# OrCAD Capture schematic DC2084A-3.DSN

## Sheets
1 PAGE6: size A
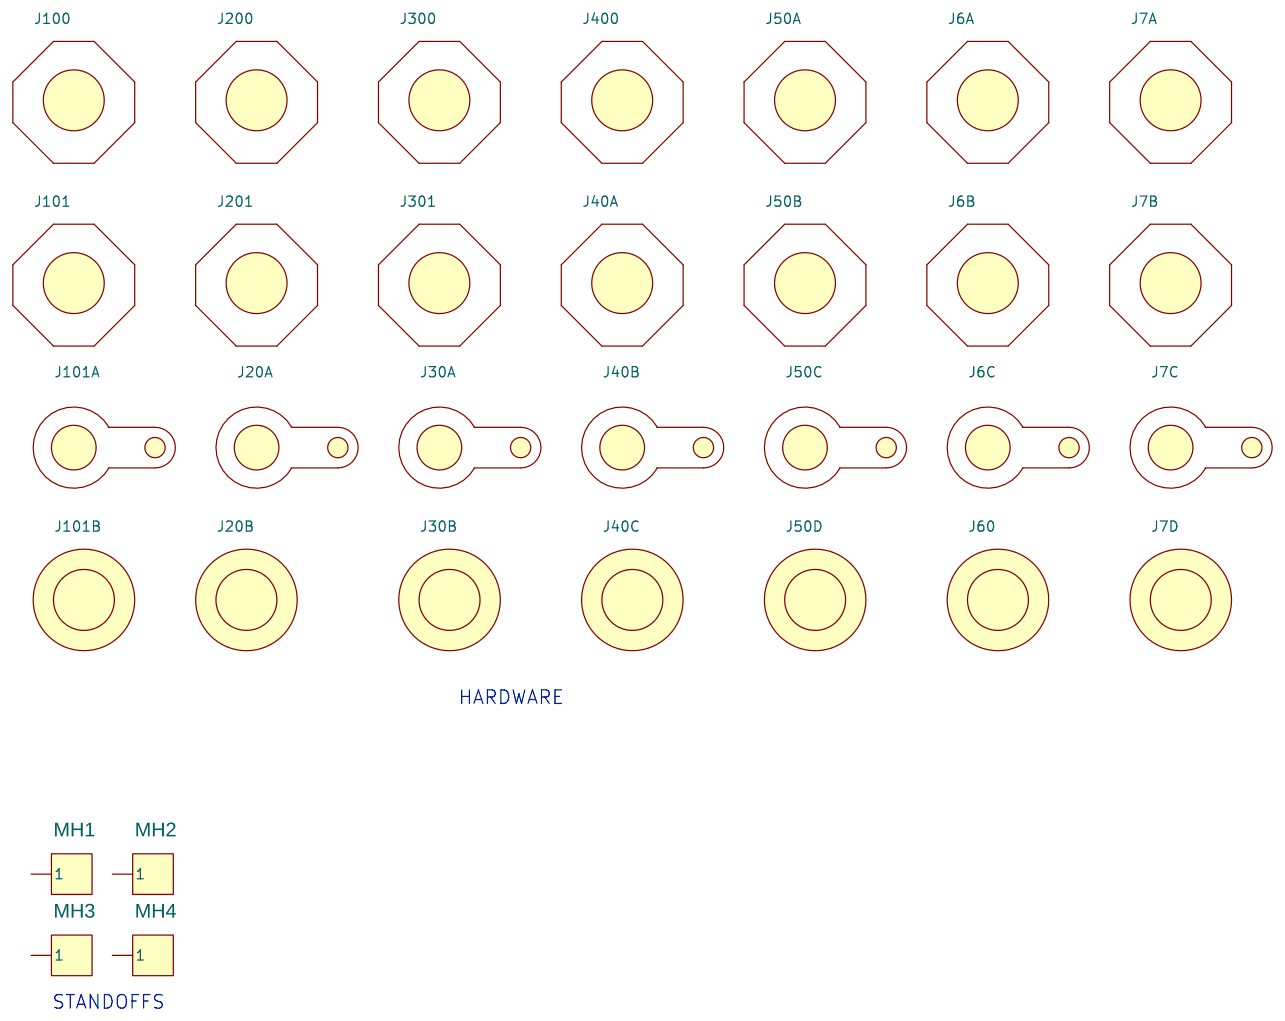
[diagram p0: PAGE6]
2 PAGE3: size Custom; title: HIGH EFFICIENCY, POLY-PHASE SYNCHRONOUS BUCK; rev: 3; company: TM; note: CONVERTER WITH POWER SYSTEM MANAGEMENT
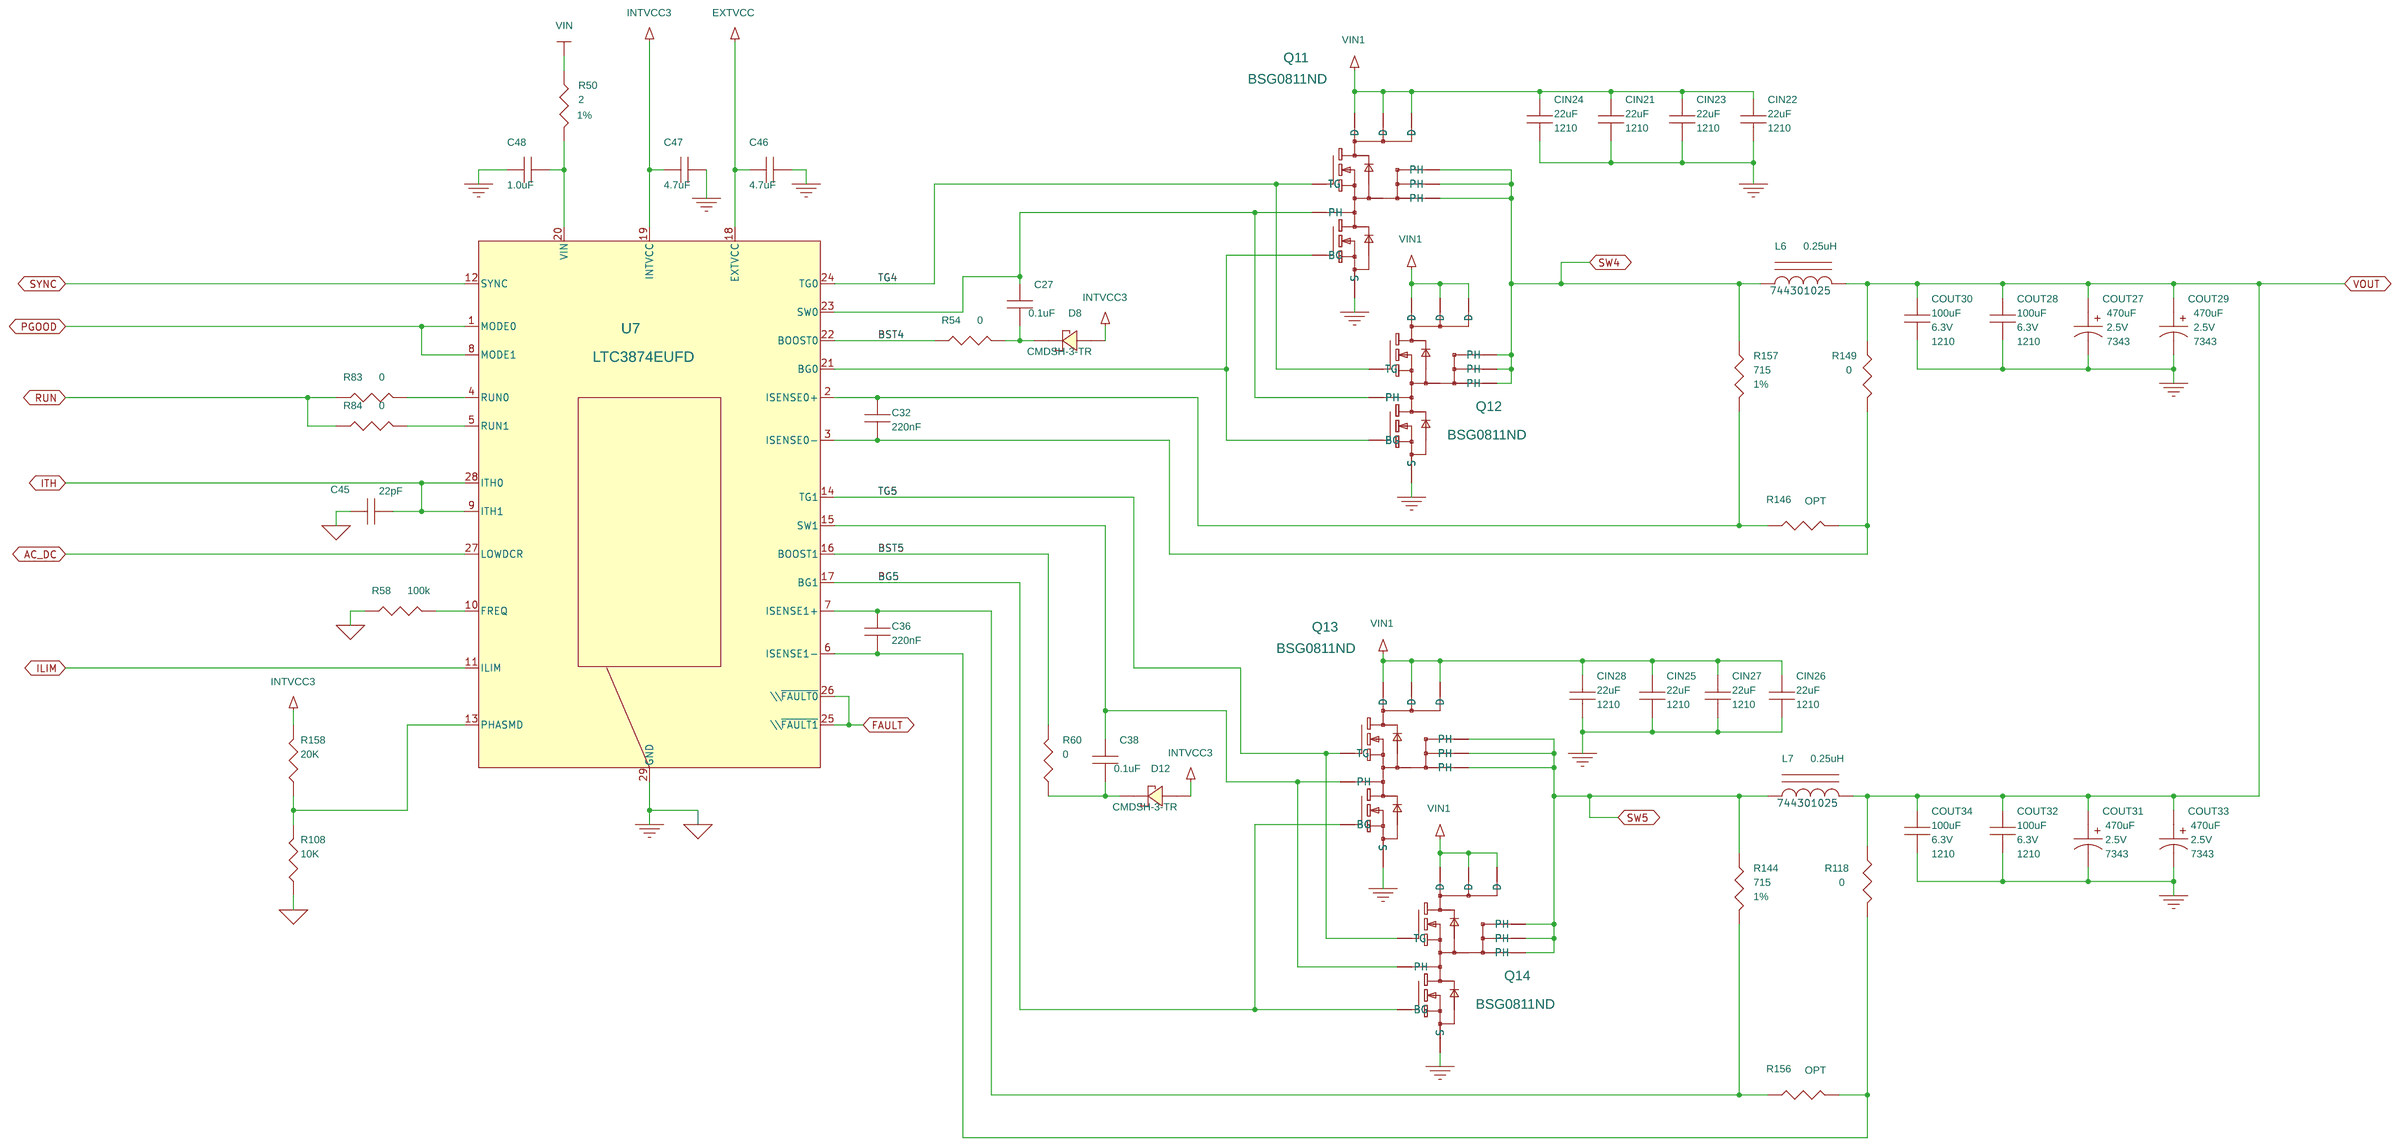
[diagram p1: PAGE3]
3 PAGE4: size B; title: HIGH EFFICIENCY, POLY-PHASE SYNCHRONOUS BUCK; rev: 3; company: TM; note: CONVERTER WITH POWER SYSTEM MANAGEMENT
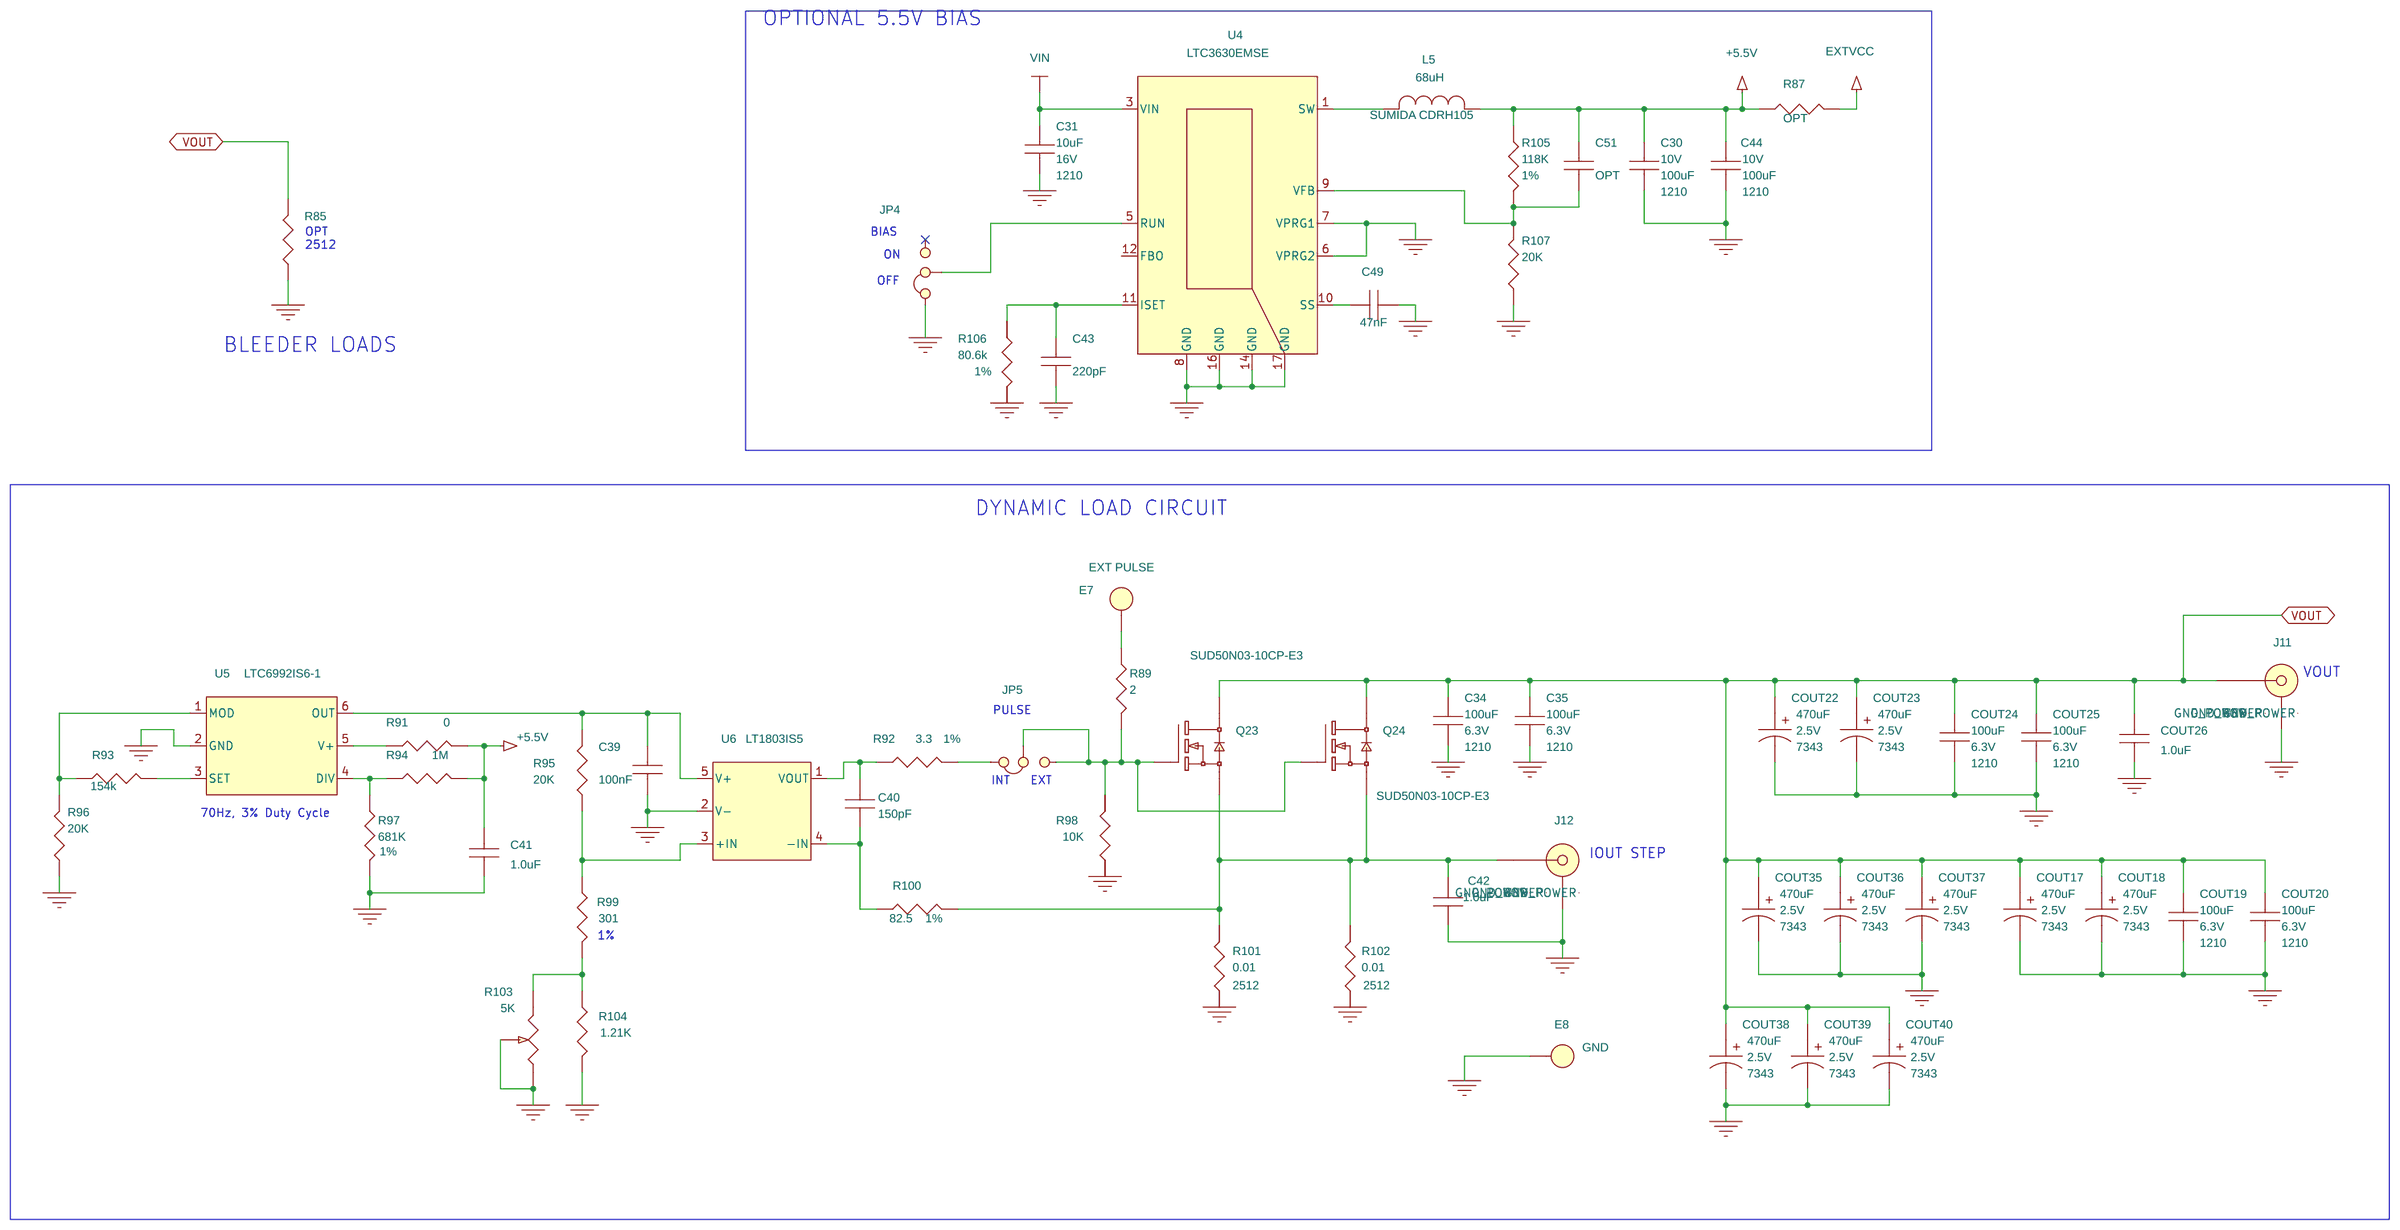
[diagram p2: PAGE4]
4 PAGE1: size Custom; title: HIGH EFFICIENCY, POLY-PHASE SYNCHRONOUS BUCK; rev: 3; company: TM; note: CONVERTER WITH POWER SYSTEM MANAGEMENT
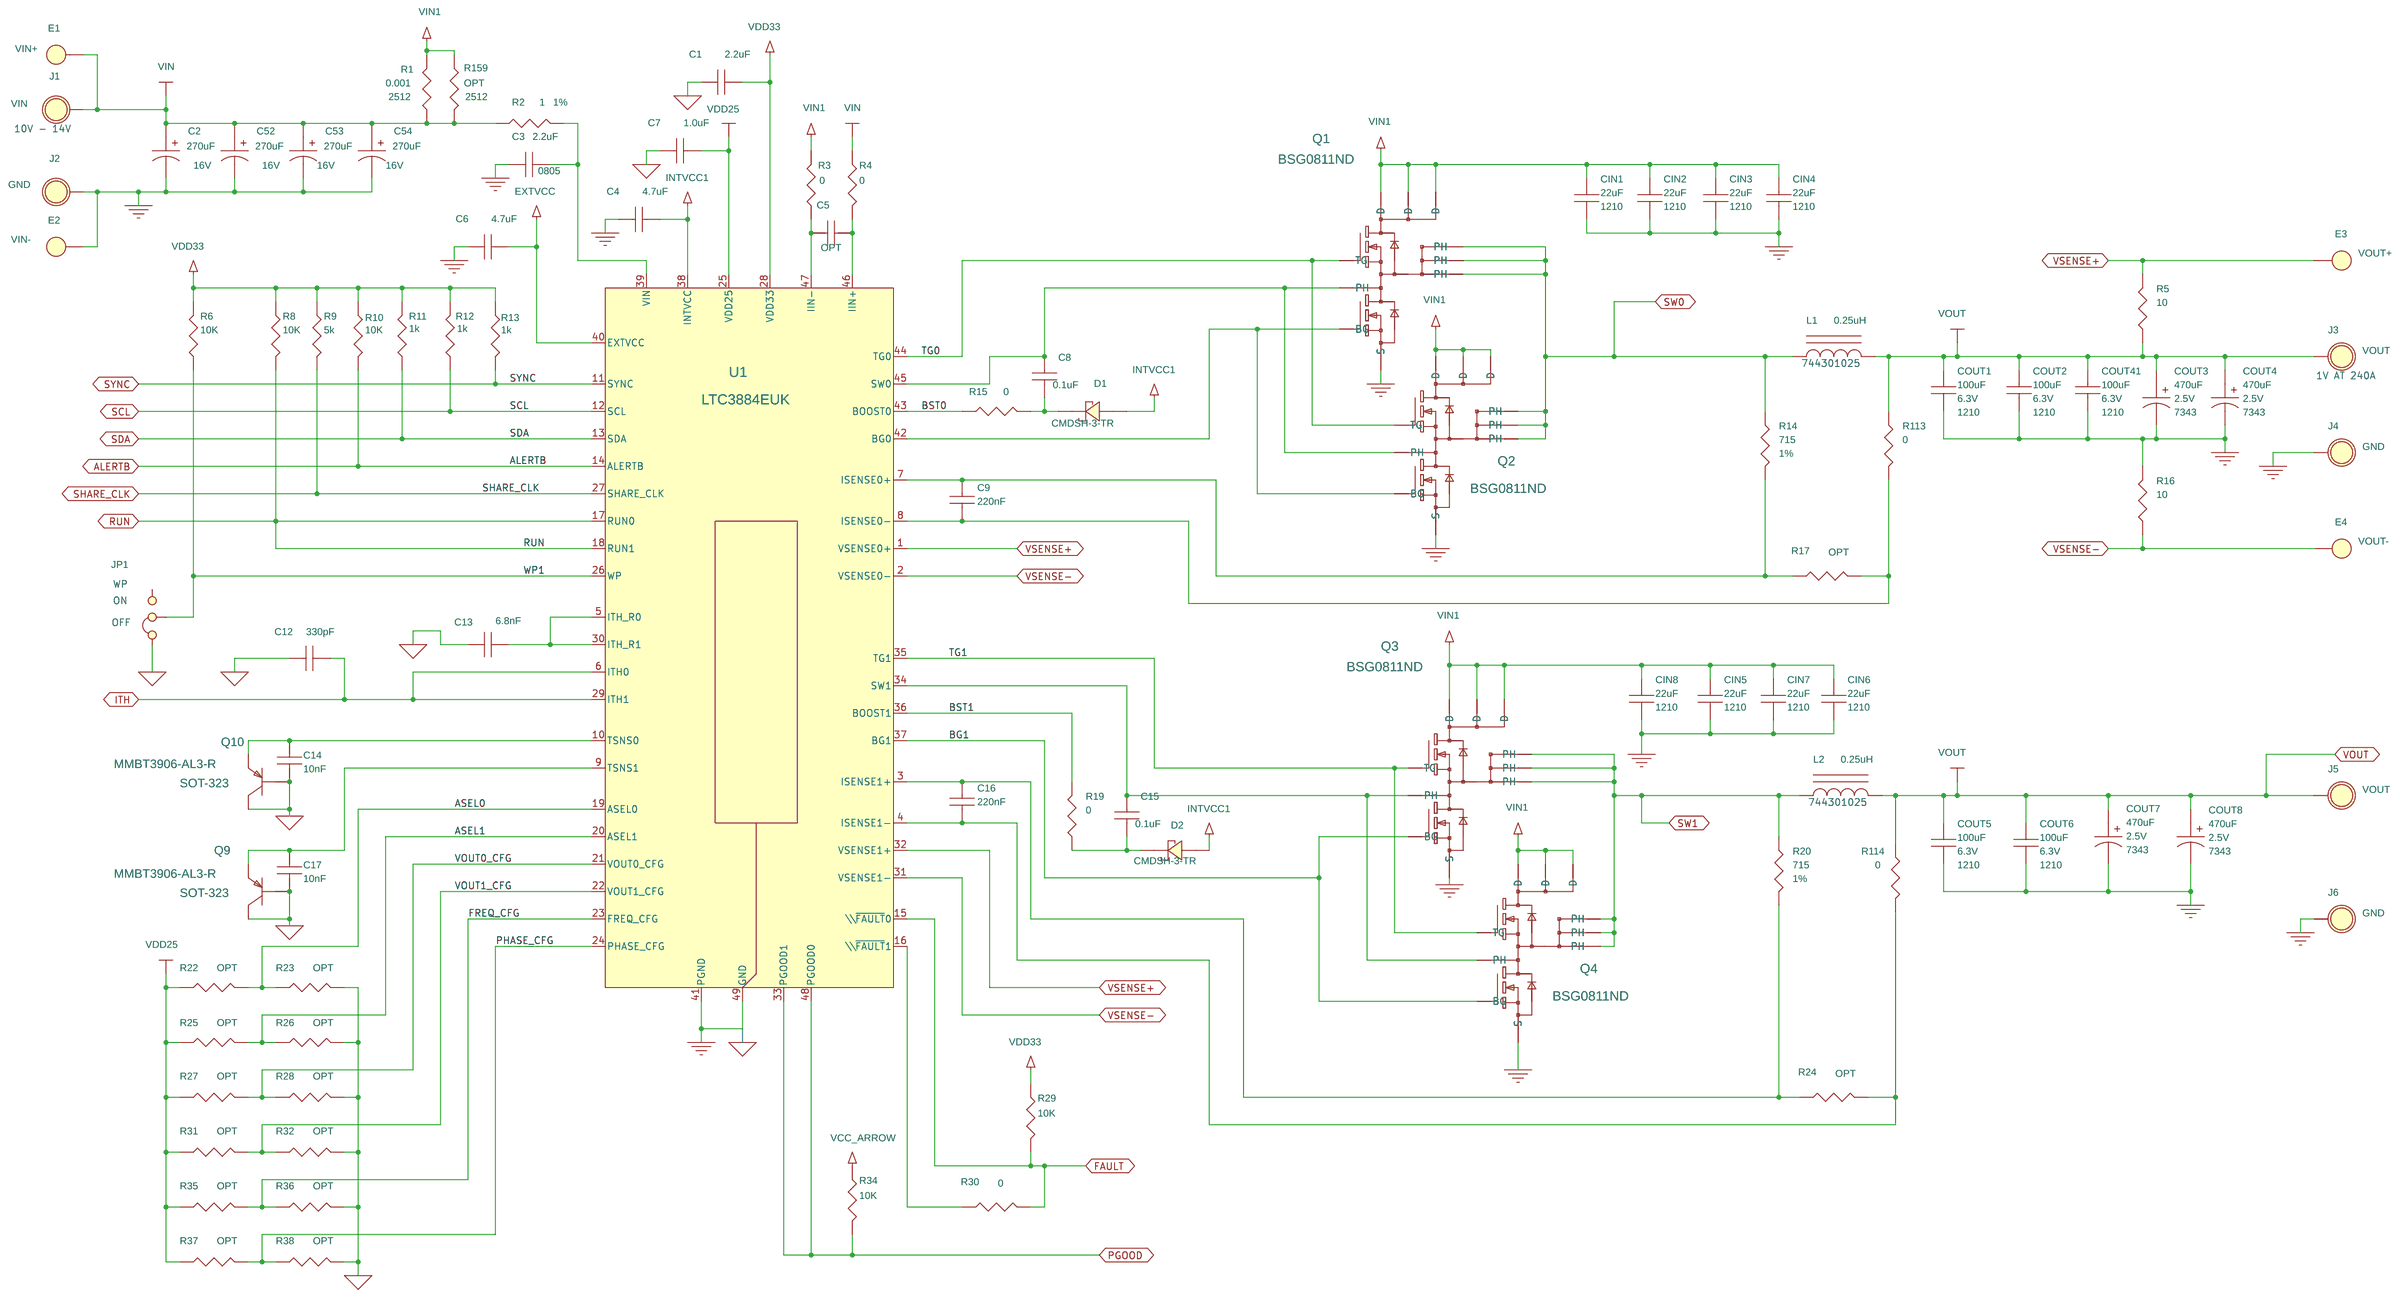
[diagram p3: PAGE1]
5 PAGE2: size Custom; title: HIGH EFFICIENCY, POLY-PHASE SYNCHRONOUS BUCK; rev: 3; company: TM; note: CONVERTER WITH POWER SYSTEM MANAGEMENT
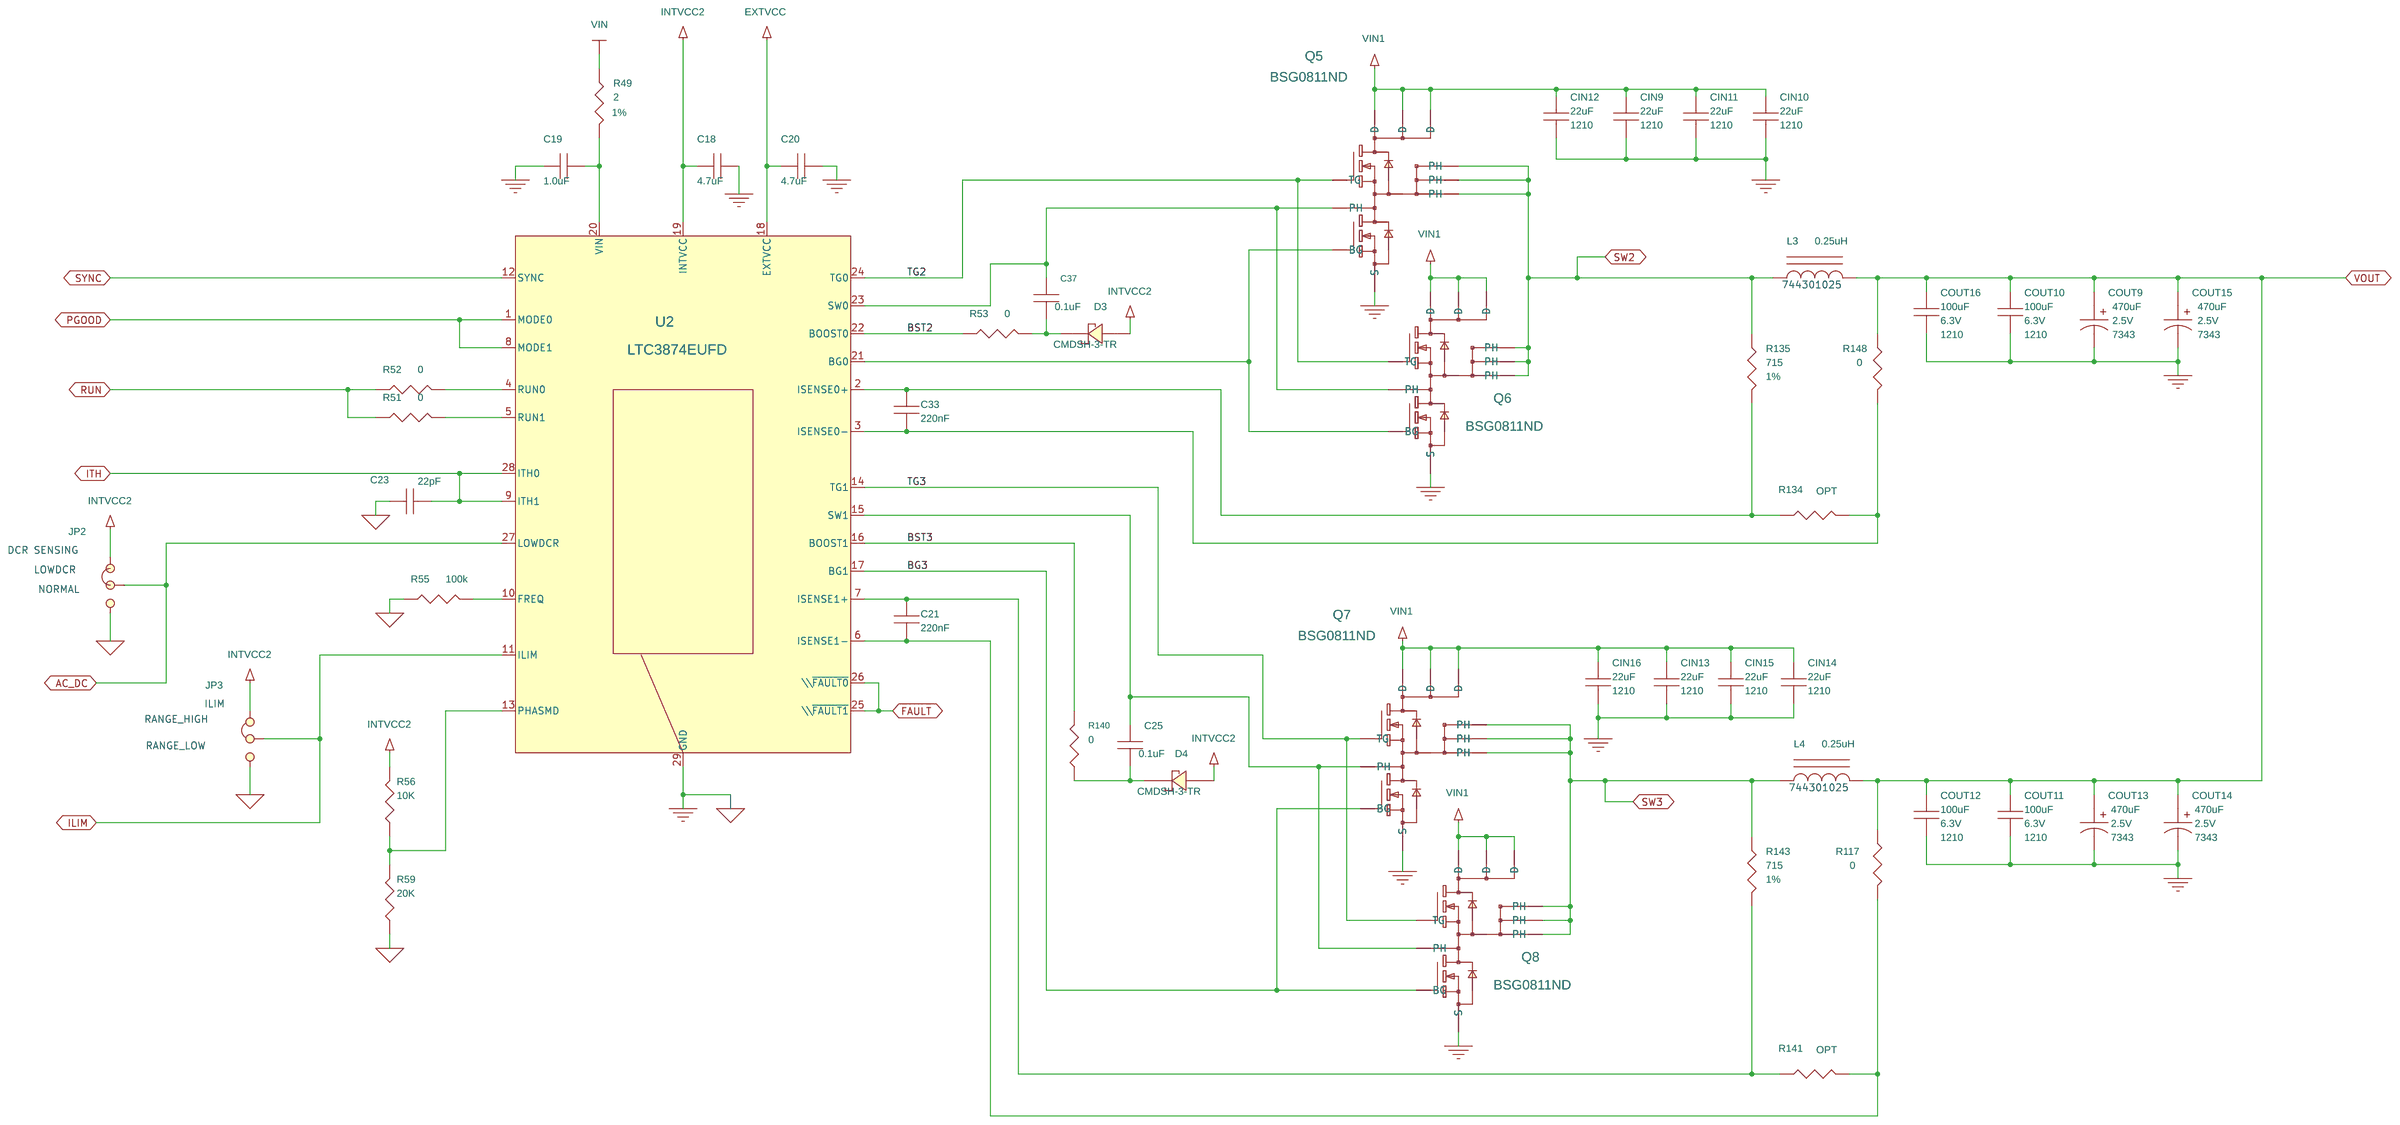
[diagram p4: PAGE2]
6 PAGE5: size B; title: HIGH EFFICIENCY, POLY-PHASE SYNCHRONOUS BUCK; rev: 3; company: TM; note: CONVERTER WITH POWER SYSTEM MANAGEMENT
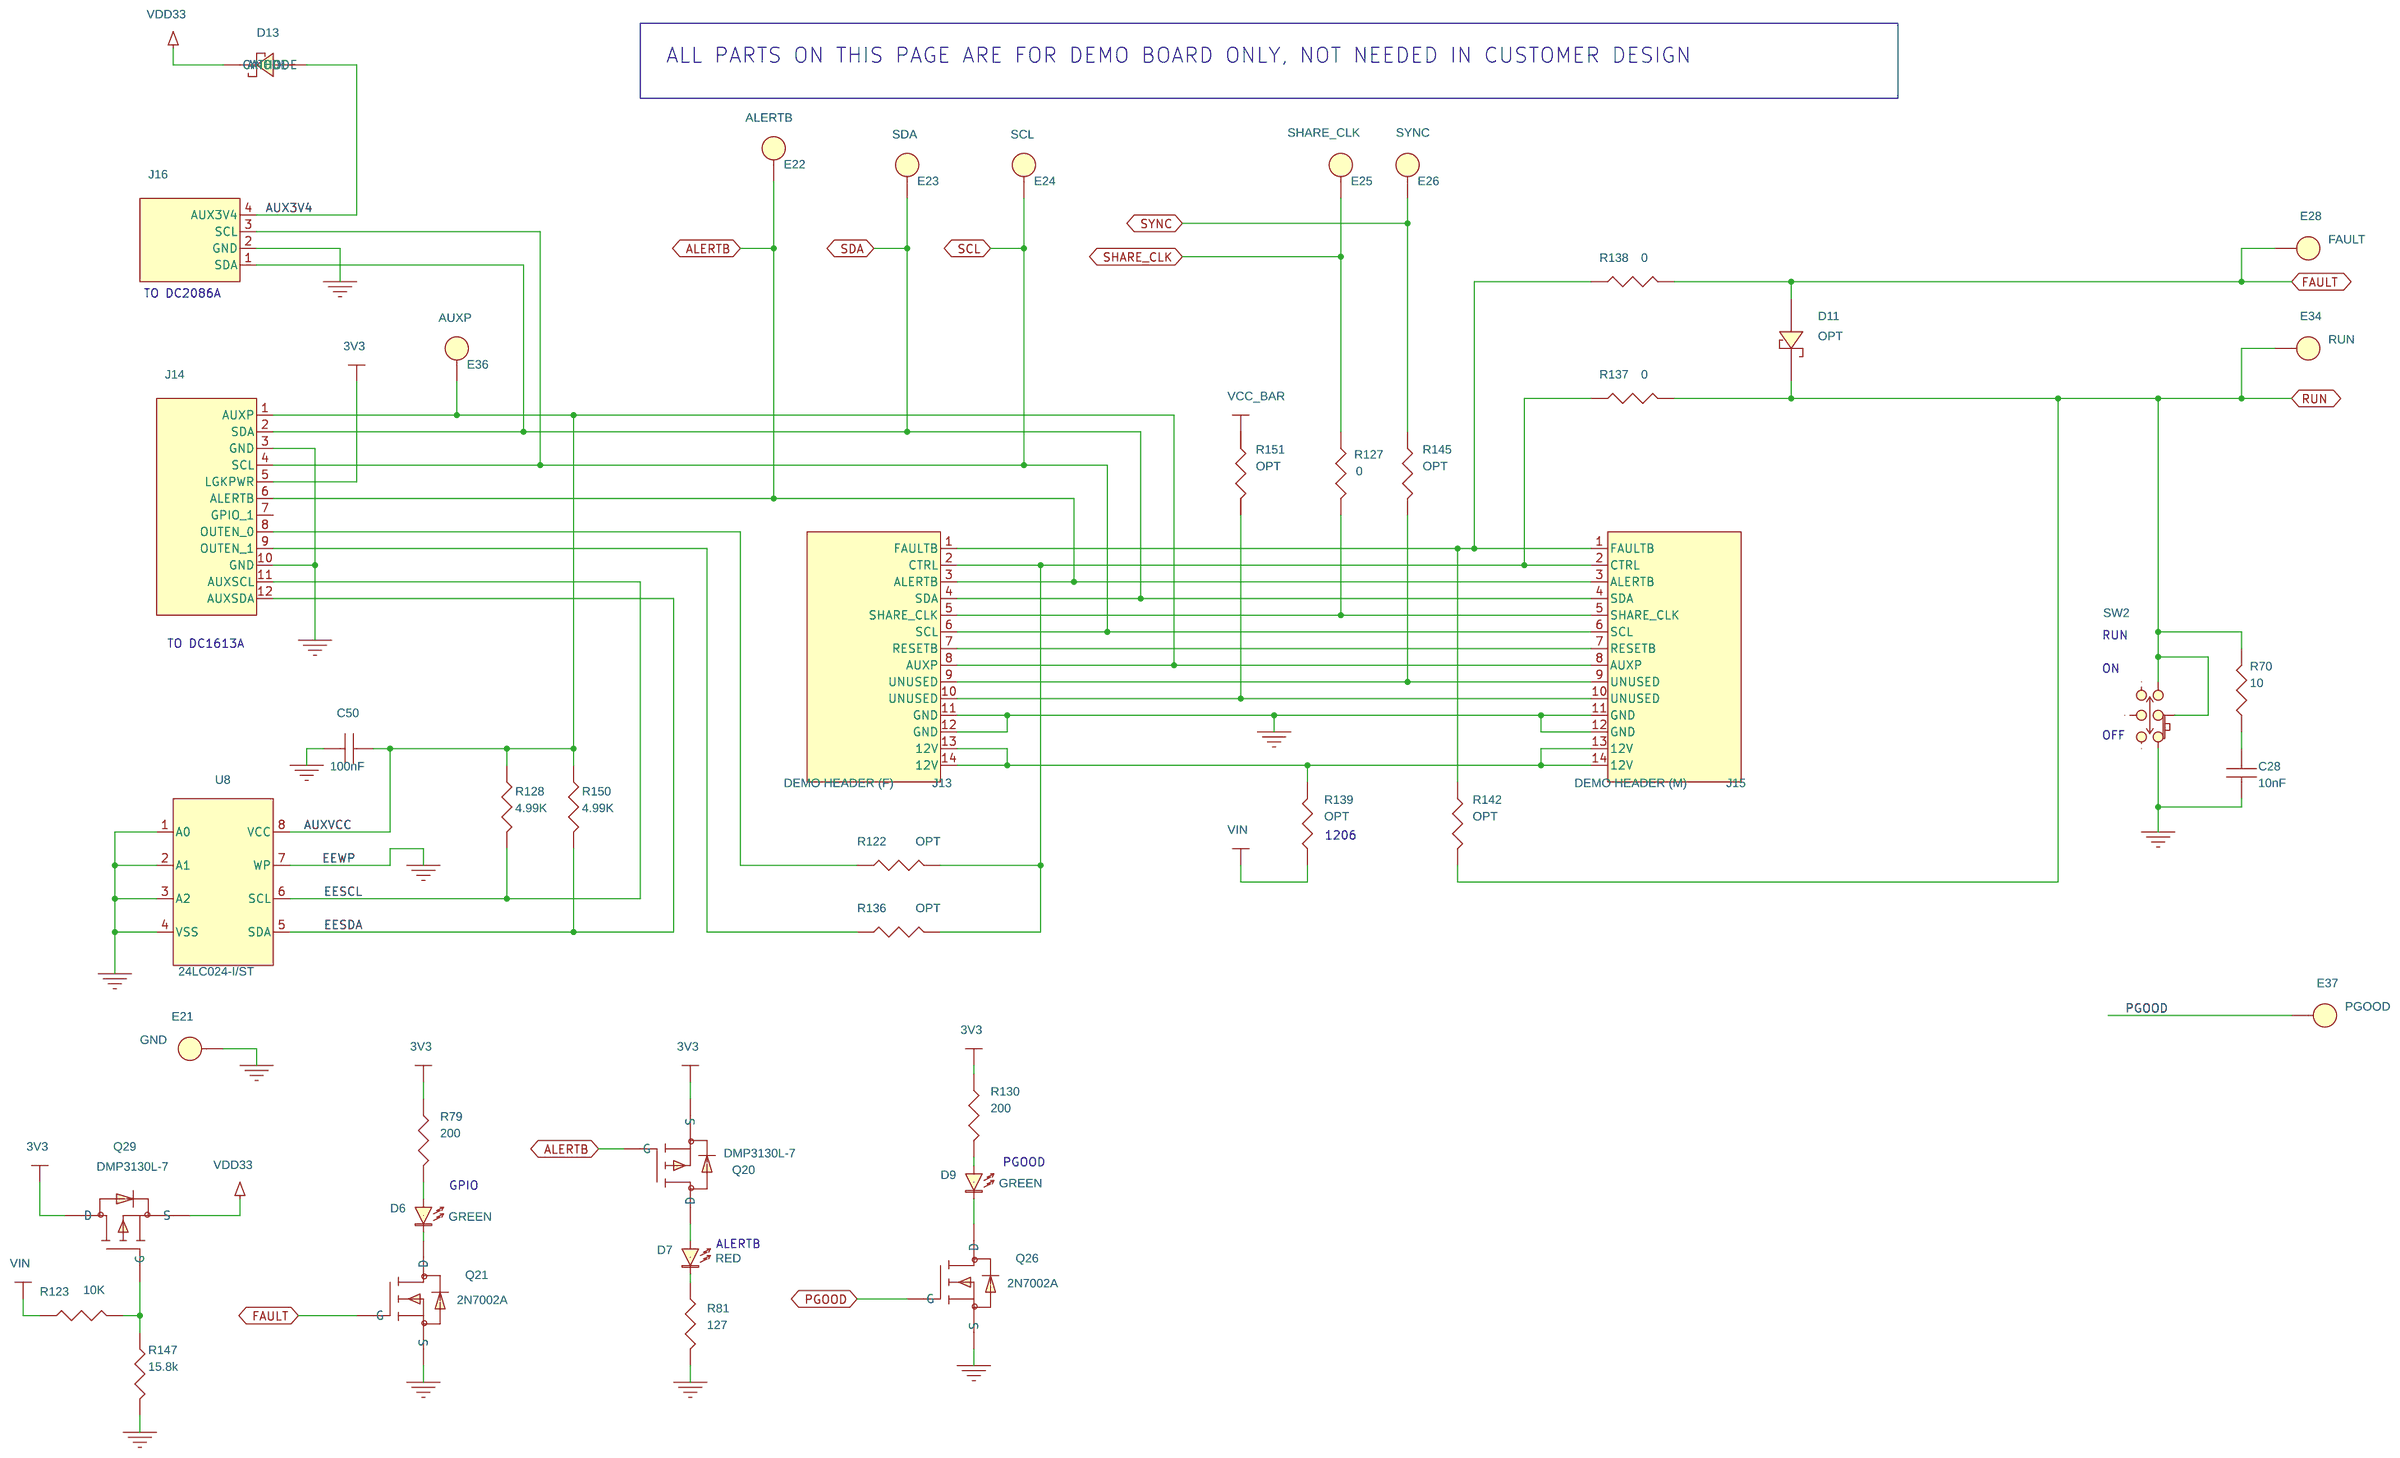
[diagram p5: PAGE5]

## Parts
sheet PAGE1
C1  2.2uF  [0603]
C2  270uF  [CAP\SAN\OSCON\SVF12]
C3  2.2uF  [0805]
C4  4.7uF  [0603]
C5  OPT  [0603]
C6  4.7uF  [0603]
C7  1.0uF  [0603]
C8  0.1uF  [0603]
C9  220nF  [0603]
C12  330pF  [0603]
C13  6.8nF  [0603]
C14  10nF  [0603]
C15  0.1uF  [0603]
C16  220nF  [0603]
C17  10nF  [0603]
C52  270uF  [CAP\SAN\OSCON\SVF12]
C53  270uF  [CAP\SAN\OSCON\SVF12]
C54  270uF  [CAP\SAN\OSCON\SVF12]
CIN1  22uF  [1210]
CIN2  22uF  [1210]
CIN3  22uF  [1210]
CIN4  22uF  [1210]
CIN5  22uF  [1210]
CIN6  22uF  [1210]
CIN7  22uF  [1210]
CIN8  22uF  [1210]
COUT1  100uF  [1210]
COUT2  100uF  [1210]
COUT3  470uF  [7343]
COUT4  470uF  [7343]
COUT5  100uF  [1210]
COUT6  100uF  [1210]
COUT7  470uF  [7343]
COUT8  470uF  [7343]
COUT41  100uF  [1210]
D1  CMDSH-3-TR  [SOD323]
D2  CMDSH-3-TR  [SOD323]
E1  VIN+  [TP\MMX\2501-2]
E2  VIN-  [TP\MMX\2501-2]
E3  VOUT+  [TP\MMX\2501-2]
E4  VOUT-  [TP\MMX\2501-2]
J1  BANANA SMALL  [CON\LUG\10]
J2  BANANA SMALL  [CON\LUG\10]
J3  BANANA SMALL  [CON\LUG\10]
J4  BANANA SMALL  [CON\LUG\10]
J5  BANANA SMALL  [CON\LUG\10]
J6  BANANA SMALL  [CON\LUG\10]
JP1  JP3X1/079\NO\12  [SIP\3P\2MM]
L1  0.25uH  [IND\WURTH\7443010XX]
L2  0.25uH  [IND\WURTH\7443010XX]
Q1  BSG0811ND  [PG-TISON8-4]
Q2  BSG0811ND  [PG-TISON8-4]
Q3  BSG0811ND  [PG-TISON8-4]
Q4  BSG0811ND  [PG-TISON8-4]
Q9  MMBT3906-AL3-R  [SOT-323]
Q10  MMBT3906-AL3-R  [SOT-323]
R1  0.001  [2512]
R2  1  [0603]
R3  0  [0603]
R4  0  [0603]
R5  10  [0603]
R6  10K  [0603]
R8  10K  [0603]
R9  5k  [0603]
R10  10K  [0603]
R11  1k  [0603]
R12  1k  [0603]
R13  1k  [0603]
R14  715  [0603]
R15  0  [0603]
R16  10  [0603]
R17  OPT  [0603]
R19  0  [0603]
R20  715  [0603]
R22  OPT  [0603]
R23  OPT  [0603]
R24  OPT  [0603]
R25  OPT  [0603]
R26  OPT  [0603]
R27  OPT  [0603]
R28  OPT  [0603]
R29  10K  [0603]
R30  0  [0603]
R31  OPT  [0603]
R32  OPT  [0603]
R34  10K  [0603]
R35  OPT  [0603]
R36  OPT  [0603]
R37  OPT  [0603]
R38  OPT  [0603]
R113  0  [0603]
R114  0  [0603]
R159  OPT  [2512]
U1  LTC3884EUK  [LT_UK48_7X7]
XJP1  SHUNT  [NONE]
sheet PAGE2
C18  4.7uF  [0603]
C19  1.0uF  [0603]
C20  4.7uF  [0603]
C21  220nF  [0603]
C23  22pF  [0603]
C25  0.1uF  [0603]
C33  220nF  [0603]
C37  0.1uF  [0603]
CIN9  22uF  [1210]
CIN10  22uF  [1210]
CIN11  22uF  [1210]
CIN12  22uF  [1210]
CIN13  22uF  [1210]
CIN14  22uF  [1210]
CIN15  22uF  [1210]
CIN16  22uF  [1210]
COUT9  470uF  [7343]
COUT10  100uF  [1210]
COUT11  100uF  [1210]
COUT12  100uF  [1210]
COUT13  470uF  [7343]
COUT14  470uF  [7343]
COUT15  470uF  [7343]
COUT16  100uF  [1210]
D3  CMDSH-3-TR  [SOD323]
D4  CMDSH-3-TR  [SOD323]
JP2  JP3X1/079\NO\12  [SIP\3P\2MM]
JP3  JP3X1/079\NO\12  [SIP\3P\2MM]
L3  0.25uH  [IND\WURTH\7443010XX]
L4  0.25uH  [IND\WURTH\7443010XX]
Q5  BSG0811ND  [PG-TISON8-4]
Q6  BSG0811ND  [PG-TISON8-4]
Q7  BSG0811ND  [PG-TISON8-4]
Q8  BSG0811ND  [PG-TISON8-4]
R49  2  [0603]
R51  0  [0603]
R52  0  [0603]
R53  0  [0603]
R55  100k  [0603]
R56  10K  [0603]
R59  20K  [0603]
R117  0  [0603]
R134  OPT  [0603]
R135  715  [0603]
R140  0  [0603]
R141  OPT  [0603]
R143  715  [0603]
R148  0  [0603]
U2  LTC3874EUFD  [LT_UFD28_4X5]
XJP2  SHUNT  [NONE]
XJP3  SHUNT  [NONE]
sheet PAGE3
C27  0.1uF  [0603]
C32  220nF  [0603]
C36  220nF  [0603]
C38  0.1uF  [0603]
C45  22pF  [0603]
C46  4.7uF  [0603]
C47  4.7uF  [0603]
C48  1.0uF  [0603]
CIN21  22uF  [1210]
CIN22  22uF  [1210]
CIN23  22uF  [1210]
CIN24  22uF  [1210]
CIN25  22uF  [1210]
CIN26  22uF  [1210]
CIN27  22uF  [1210]
CIN28  22uF  [1210]
COUT27  470uF  [7343]
COUT28  100uF  [1210]
COUT29  470uF  [7343]
COUT30  100uF  [1210]
COUT31  470uF  [7343]
COUT32  100uF  [1210]
COUT33  470uF  [7343]
COUT34  100uF  [1210]
D8  CMDSH-3-TR  [SOD323]
D12  CMDSH-3-TR  [SOD323]
L6  0.25uH  [IND\WURTH\7443010XX]
L7  0.25uH  [IND\WURTH\7443010XX]
Q11  BSG0811ND  [PG-TISON8-4]
Q12  BSG0811ND  [PG-TISON8-4]
Q13  BSG0811ND  [PG-TISON8-4]
Q14  BSG0811ND  [PG-TISON8-4]
R50  2  [0603]
R54  0  [0603]
R58  100k  [0603]
R60  0  [0603]
R83  0  [0603]
R84  0  [0603]
R108  10K  [0603]
R118  0  [0603]
R144  715  [0603]
R146  OPT  [0603]
R149  0  [0603]
R156  OPT  [0603]
R157  715  [0603]
R158  20K  [0603]
U7  LTC3874EUFD  [LT_UFD28_4X5]
sheet PAGE4
C30  100uF  [1210]
C31  10uF  [1210]
C34  100uF  [1210]
C35  100uF  [1210]
C39  100nF  [0603]
C40  150pF  [0603]
C41  1.0uF  [0603]
C42  1.0uF  [0603]
C43  220pF  [0603]
C44  100uF  [1210]
C49  47nF  [0603]
C51  OPT  [0603]
COUT17  470uF  [7343]
COUT18  470uF  [7343]
COUT19  100uF  [1210]
COUT20  100uF  [1210]
COUT22  470uF  [7343]
COUT23  470uF  [7343]
COUT24  100uF  [1210]
COUT25  100uF  [1210]
COUT26  1.0uF  [0603]
COUT35  470uF  [7343]
COUT36  470uF  [7343]
COUT37  470uF  [7343]
COUT38  470uF  [7343]
COUT39  470uF  [7343]
COUT40  470uF  [7343]
E7  EXT PULSE  [TP\MMX\2501-2]
E8  GND  [TP\MMX\2501-2]
J11  XXX  [BNC5]
J12  XXX  [BNC5]
JP4  JP3X1/079\NO\12  [SIP\3P\2MM]
JP5  JP3X1/079\NO\12  [SIP\3P\2MM]
L5  68uH  [IND\SUMIDA\CDRH105R\12X12]
Q23  SUD50N03-10CP-E3  [TO-252]
Q24  SUD50N03-10CP-E3  [TO-252]
R85  OPT  [2512]
R87  OPT  [0603]
R89  2  [0603]
R91  0  [0603]
R92  3.3  [0603]
R93  154k  [0603]
R94  1M  [0603]
R95  20K  [0603]
R96  20K  [0603]
R97  681K  [0603]
R98  10K  [0603]
R99  301  [0603]
R100  82.5  [0603]
R101  0.01  [2512]
R102  0.01  [2512]
R103  5K  [BOURNS_3386P]
R104  1.21K  [0603]
R105  118K  [0603]
R106  80.6k  [0603]
R107  20K  [0603]
U4  LTC3630EMSE  [MSE-16L(12)]
U5  LTC6992IS6-1  [LT_S6]
U6  LT1803IS5  [LT_S5]
XJP4  SHUNT  [NONE]
XJP5  SHUNT  [NONE]
sheet PAGE5
C28  10nF  [0603]
C50  100nF  [0603]
D6  GREEN  [LED_0603]
D7  RED  [LED_0603]
D9  GREEN  [LED_0603]
D11  OPT  [SOD323]
D13  DIODE SCHOTTKY  [SOD882]
E21  GND  [TP\MMX\2501-2]
E22  ALERTB  [TP\MMX\2501-2]
E23  SDA  [TP\MMX\2501-2]
E24  SCL  [TP\MMX\2501-2]
E25  SHARE_CLK  [TP\MMX\2501-2]
E26  SYNC  [TP\MMX\2501-2]
E28  FAULT  [TP\MMX\2501-2]
E34  RUN  [TP\MMX\2501-2]
E36  AUXP  [TP\MMX\2501-2]
E37  PGOOD  [TP\MMX\2501-2]
J13  DEMO HEADER (F)  [NPPN072FJFN-RC]
J14  HD2X6-079  [HD2X6-079-MOLEX]
J15  DEMO HEADER (M)  [NPPN072FJFN]
J16  HD2X6-079-PMBUS_0  [CON\HRS\DF3A-4P-2DSA]
Q20  DMP3130L-7  [SOT23]
Q21  2N7002A  [SOT23]
Q26  2N7002A  [SOT23]
Q29  DMP3130L-7  [SOT23]
R70  10  [0603]
R79  200  [0603]
R81  127  [0603]
R122  OPT  [0603]
R123  10K  [0603]
R127  0  [0603]
R128  4.99K  [0603]
R130  200  [0603]
R136  OPT  [0603]
R137  0  [0603]
R138  0  [0603]
R139  OPT  [1206]
R142  OPT  [0603]
R145  OPT  [0603]
R147  15.8k  [0603]
R150  4.99K  [0603]
R151  OPT  [0603]
SW2  JP3X1/079\NO\12  [JS202011]
U8  24LC024-I/ST  [TSSOP-8_4.4MM]
sheet PAGE6
J6A  NUT
J6B  NUT
J6C  Lug_Ring
J7A  NUT
J7B  NUT
J7C  Lug_Ring
J7D  Washer
J20A  Lug_Ring
J20B  Washer
J30A  Lug_Ring
J30B  Washer
J40A  NUT
J40B  Lug_Ring
J40C  Washer
J50A  NUT
J50B  NUT
J50C  Lug_Ring
J50D  Washer
J60  Washer
J100  NUT
J101  NUT
J101A  Lug_Ring
J101B  Washer
J200  NUT
J201  NUT
J300  NUT
J301  NUT
J400  NUT
MH1  CON1  [KEYSTONE_8831]
MH2  CON1  [KEYSTONE_8831]
MH3  CON1  [KEYSTONE_8831]
MH4  CON1  [KEYSTONE_8831]

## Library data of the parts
C1 = CAP_NP: CAP, 0603 2.2uF 20% 6.3V X5R; Part Number: TAIYO YUDEN JMK105BJ225MV-T; Volts/Amps/Watts: 50V
C2 C52-C54 = CAPR12X5_0: CAP, 270uF 20% 16V OSCON; Component: cap; Manufacturer: SANYO; Part Number: PANASONIC 16SVPC270M; Tolerance: 20%; Type: OS-CON; Volts/Amps/Watts: 16V
C3 = CAP_NP_0: CAP, 0805 2.2uF 10% 16V X7R; Part Number: MURATA GRM21BR71C225KA12L; VOLTAGE: 16V
C4 C6 C18 C20 C46 C47 = CAP_NP: CAP, 0603 4.7uF 10% 10V X5R; Part Number: AVX 0603ZD475KAT2A
C5 C51 = CAP_NP: CAP, 0603 OPTION; Part Number: OPTION
C7 C19 C41 C48 COUT26 = CAP_NP: CAP, 0603 1uF 20% 25V X5R; Part Number: AVX 06033D105MAT2A
C8 C15 C25 C27 C37 C38 = CAP_NP_0: CAP, 0603 0.1uF 10% 25V X5R; Part Number: AVX 06033C104KAT2A; VOLTAGE: 50V
C9 C16 C21 C32 C33 C36 = CAP_NP: CAP, 0603 220nF 10% 25V X7R; Part Number: TDK C1608X7R1E224K
C12 = CAP_NP: CAP, 0603 330pF 5% 50V C0G; Part Number: MURATA GRM1885C1H331JD01D
C13 = CAP_NP: CAP, 0603 6.8nF 10% 50V X7R; Part Number: MURATA GRM188R71H682KA01B
C14 C17 C28 = CAP_NP: CAP, 0603 10nF 10% 25V X7R; Part Number: AVX 06033C103KAT2A
CIN1-CIN16 CIN21-CIN28 = CAP_NP_0: CAP, 1210 22uF 10% 25V X7R; Part Number: MURATA GRM32ER71E226KE15L; VOLTAGE: 50V; Volts/Amps/Watts: 6.3V
C34 C35 COUT1 COUT2 COUT5 COUT6 COUT10-COUT12 COUT16 COUT19 COUT20 COUT24 COUT25 COUT28 COUT30 COUT32 COUT34 COUT41 = CAP_NP_0: CAP, 1210 100uF 20% 6.3V X5R; Part Number: TDK C3225X5R0J107M; VOLTAGE: 50V; Volts/Amps/Watts: 6.3V
COUT3 COUT4 COUT7-COUT9 COUT13-COUT15 COUT17 COUT18 COUT22 COUT23 COUT27 COUT29 COUT31 COUT33 COUT35-COUT40 = t510x337k010as: CAP, 7343 470uF 20% 2.5V TANT. POLYMER; 1st Part Field: 2.5V; 3rd Part Field: POSCAP; Part Number: PANASONIC ETPF470M5H
D1-D4 D8 D12 = DIODE_SCHOTTKY_9: DIODE, SCHOTTKY 30V, 100mA; Part Number: CENTRAL SEMI CMDSH-3-TR
E1-E4 E7 E8 E21-E26 E28 E34 E36 E37 = E_0: TURRET; Part Number: MILL MAX 2501-2-00-80-00-00-07-0
J1 = BANANA_SMALL_0: STUD, TEST PIN; Component: conn; Label: VIN; Part Number: PEM KFH-032-10
J2 J4 J6 = BANANA_SMALL_0: STUD, TEST PIN; Component: conn; Label: GND; Part Number: PEM KFH-032-10
J3 J5 = BANANA_SMALL_0: STUD, TEST PIN; Component: conn; Label: VOUT; Part Number: PEM KFH-032-10
JP1-JP5 = JP3X1_079_NO_12_1: HEADER, SINGLE ROW 3PIN; Part Number: WURTH ELEKTRONIK 60800213421
L1-L4 L6 L7 = INDUCTOR_IRON: IND, 0.25uH; Part Number: WURTH ELEKTRONIK 744301025
Q1-Q8 Q11-Q14 = FDMS3610S_3: XSTR, DUAL CHANNEL OptiMOS MOSFET; Part Number: INFINEON BSG0811ND
Q9 Q10 = MMBT3906_SOT_0: XSTR, PNP GENERAL PURPOSE; Part Number: DIODES INC. MMST3906-7-F
R1 = RES0603_0: RES, 2512 0.001 OHMS 1% 1W; Label: 2; Manufacturer: Rohm; Manufacturer P/N: RHM0.0GCT-ND; Part Number: VISHAY WSL25121L000FEA; Vendor: Digikey; Vendor P/N: RHM0.0GCT-ND; Volts/Amps/Watts: 0.1W
R2 = RES0603_0: RES, 0603 1 OHMS 1% 1/10W; Component: res; Label: <label>; Manufacturer: Panasonic; Manufacturer P/N: ERJ-3EKF5901V; Part Number: VISHAY CRCW06031R00FNEA; Tolerance: 1%; Vendor: Digikey; Vendor P/N: P5.90KHCT-ND; Volts/Amps/Watts: 0.1W
R3 R127 = RES0603_0: RES, 0603 0 OHMS JUMPER; Manufacturer: Rohm; Manufacturer P/N: RHM0.0GCT-ND; Part Number: VISHAY CRCW06030000Z0EA; Tolerance: 5%; Vendor: Digikey; Vendor P/N: RHM0.0GCT-ND; Volts/Amps/Watts: 0.1W
R4 = RES0603_0: RES, 0603 0 OHMS JUMPER; Manufacturer: ROHM; Manufacturer P/N: MCR03EZPFX1002; Part Number: VISHAY CRCW06030000Z0EA; Vendor: Digikey; Vendor P/N: RHM10.0KHCT-ND; Volts/Amps/Watts: 0.1W
R5 = RES0603_0: RES, 0603 10 OHMS 1% 0.1W; Manufacturer: Yageo; Manufacturer P/N: RC0603JR-070RL; Part Number: VISHAY CRCW060310R0FKEA; Tolerance: 1%; Vendor: Digikey; Vendor P/N: 311-0.0GRCT-ND; Volts/Amps/Watts: 0.1W
R6 R56 R108 = RES0603_0: RES, 0603 10K OHMS 5% 0.1W; Manufacturer: Panasonic; Manufacturer P/N: ERJ-3EKF2002V; Part Number: VISHAY CRCW060310K0JNEA; Vendor: Digikey; Vendor P/N: P20.0KHCT-ND; Volts/Amps/Watts: 0.1W
R8 R10 = RES0603_0: RES, 0603 10K OHMS 5% 0.1W; Manufacturer: ROHM; Manufacturer P/N: MCR03EZPFX1002; Part Number: VISHAY CRCW060310K0JNEA; Vendor: Digikey; Vendor P/N: RHM10.0KHCT-ND; Volts/Amps/Watts: 0.1W
R9 = RES0603_0: RES, 0603 5k OHMS 5% 0.1W; Manufacturer: ROHM; Manufacturer P/N: MCR03EZPFX1002; Part Number: VISHAY CRCW06035K00JNED; Vendor: Digikey; Vendor P/N: RHM10.0KHCT-ND; Volts/Amps/Watts: 0.1W
R11-R13 = RES0603_0: RES, 0603 1K OHMS 5% 0.1W; Manufacturer: ROHM; Manufacturer P/N: MCR03EZPFX1002; Part Number: VISHAY CRCW06031K00JNEA; Vendor: Digikey; Vendor P/N: RHM10.0KHCT-ND; Volts/Amps/Watts: 0.1W
R14 R135 R157 = R_1: RES, 0603 715 OHMS 1% 0.1W; %: 0.1%; Part Number: VISHAY CRCW0603715RFKEA; Tol: 1%
R15 R19 R51-R54 R60 R83 R84 R91 R140 = RES0603_0: RES, 0603 0 OHMS JUMPER; Component: res; Label: <label>; Manufacturer: Panasonic; Manufacturer P/N: ERJ-3EKF5901V; Part Number: VISHAY CRCW06030000Z0EA; Tolerance: 1%; Vendor: Digikey; Vendor P/N: P5.90KHCT-ND; Volts/Amps/Watts: 0.1W
R16 = RES0603_0: RES, 0603 10 OHMS 1% 1/10W; Manufacturer: Yageo; Manufacturer P/N: RC0603JR-070RL; Part Number: VISHAY CRCW060310R0FKEA; Tolerance: 1%; Vendor: Digikey; Vendor P/N: 311-0.0GRCT-ND; Volts/Amps/Watts: 0.1W
R17 R24 R134 R141 R146 R156 = R_1: RES, 0603 OPTION; %: 0.1%; Part Number: OPTION
R20 = R_1: RES, 0603 715 OHMS 1% 0.1W; %: 1%; Part Number: VISHAY CRCW0603715RFKEA
R22 R28 R32 R36 R38 = RES0603_0: RES, 0603 OPTION; Manufacturer: Panasonic; Manufacturer P/N: ERJ-3EKF2002V; Part Number: OPTION; Vendor: Digikey; Vendor P/N: P20.0KHCT-ND; Volts/Amps/Watts: 0.1W
R23 = RES0603_0: RES, 0603 OPTION; Manufacturer: Rohm; Manufacturer P/N: RHM0.0GCT-ND; Part Number: OPTION; Tolerance: 5%; Vendor: Digikey; Vendor P/N: RHM0.0GCT-ND; Volts/Amps/Watts: 0.1W
R25 = RES0603_0: RES, 0603 OPTION; Manufacturer: Panasonic; Manufacturer P/N: ERJ-3EKF5901V; Part Number: OPTION; Vendor: Digikey; Vendor P/N: P5.90KHCT-ND; Volts/Amps/Watts: 0.1W
R26 = RES0603_0: RES, 0603 OPTION; Manufacturer: Panasonic; Manufacturer P/N: ERJ-3EKF2002V; Part Number: OPTION; Tolerance: 5%; Vendor: Digikey; Vendor P/N: P20.0KHCT-ND; Volts/Amps/Watts: 0.1W
R27 = RES0603_0: RES, 0603 OPTION; Manufacturer: Panasonic; Manufacturer P/N: ERJ-3EKF1000V; Part Number: OPTION; Vendor: Digikey; Vendor P/N: P100HCT-ND; Volts/Amps/Watts: 0.1W
R29 R34 = RES0603_0: RES, 0603 10K OHMS 5% .01W; Manufacturer: Panasonic; Manufacturer P/N: ERJ-3EKF2002V; Part Number: VISHAY CRCW060310K0JNEA; Vendor: Digikey; Vendor P/N: P20.0KHCT-ND; Volts/Amps/Watts: 0.1W
R30 = R_1: RES, 0603 0 OHMS JUMPER; %: 0.1%; Part Number: VISHAY CRCW06030000Z0EA
R31 = RES0603_0: RES, 0603 OPTION; Manufacturer: Panasonic; Manufacturer P/N: ERJ-3EKF1021V; Part Number: OPTION; Vendor: Digikey; Vendor P/N: P1.02KHCT-ND; Volts/Amps/Watts: 0.1W
R35 R37 = RES0603_0: RES, 0603 OPTION; Manufacturer: ROHM; Manufacturer P/N: MCR03EZPFX1002; Part Number: OPTION; Vendor: Digikey; Vendor P/N: RHM10.0KHCT-ND; Volts/Amps/Watts: 0.1W
R113 R114 R117 R118 R148 R149 = R_1: RES, 0603 0 OHMS JUMPER; %: 0.1%; Part Number: VISHAY CRCW06030000Z0EA; Tol: 1%
R159 = RES0603_0: RES, 2512 OPTION; Label: 2; Manufacturer: Rohm; Manufacturer P/N: RHM0.0GCT-ND; Part Number: OPTION; Vendor: Digikey; Vendor P/N: RHM0.0GCT-ND; Volts/Amps/Watts: 0.1W
U1 = LTC3880-M0001_9: IC, DUAL OUTPUT STEP-DOWN CONTROLLER; Component: IC; Manufacturer: LTC; Manufacturer P/N: LTC3880_M0001; Part Number: LINEAR TECH. LTC3884EUK
XJP1-XJP5 = SHUNT: Part Number: WURTH ELEKTRONIK 60800213421
C23 C45 = CAP_NP: CAP, 0603 22pF 5% 50V C0G; Part Number: MURATA GRM1885C1H220JA01B
R49 R50 = RES0603_0: RES, 0603 2 OHMS 1% 0.1W; Component: res; Label: <label>; Manufacturer: Panasonic; Manufacturer P/N: ERJ-3EKF5901V; Part Number: VISHAY CRCW06032R0FKEA; Tolerance: 1%; Vendor: Digikey; Vendor P/N: P5.90KHCT-ND; Volts/Amps/Watts: 0.1W
R55 R58 = RES0603_0: RES, 0603 100K OHMS 5% 0.1W; Component: res; Label: <label>; Manufacturer: Panasonic; Manufacturer P/N: ERJ-3EKF5901V; Part Number: VISHAY CRCW0603100KJNEA; Tolerance: 1%; Vendor: Digikey; Vendor P/N: P5.90KHCT-ND; Volts/Amps/Watts: 0.1W
R59 R95 R96 R107 R158 = RES0603_0: RES, 0603 20K OHMS 5% 0.1W; Manufacturer: Panasonic; Manufacturer P/N: ERJ-3EKF2002V; Part Number: VISHAY CRCW060320K0JNEA; Vendor: Digikey; Vendor P/N: P20.0KHCT-ND; Volts/Amps/Watts: 0.1W
R143 R144 = R_1: RES, 0603 715 OHMS 1% 0.1W; %: 1%; Part Number: VISHAY CRCW0603715RFKEA; Tol: 1%
U2 U7 = LTC3880-M0001_10: IC, STEP-DOWN SLAVE CONTROLLER; Component: IC; Manufacturer: LTC; Manufacturer P/N: LTC3880_M0001; Part Number: LINEAR TECH.LTC3874EUFD; Part Type: LTC3880EUF
C30 C44 = CAP_NP: CAP, 1210 100uF 20% 10V X5R; 1ST PART FIELD: 10V; Part Number: MURATA GRM32ER61A107ME20L
C31 = CAP_NP_1: CAP, 1210 10uF 10% 16V X7R; Part Number: MURATA GRM32DR71C106KA01; Voltage: 16V
C39 C50 = CAP_NP: CAP, 0603 100nF 20% 16V X7R; Part Number: AVX 0603YC104MAT2A
C40 = CAP_NP: CAP, 0603 150pF 5% 50V NPO; Part Number: AVX 06035A151JAT2A
C42 = CAP_NP_1: CAP, 0603 1uF 20% 25V X5R; Part Number: AVX 06033D105MAT2A
C43 = CAP_NP: CAP, 0603 220pF 10% 50V X7R; Part Number: AVX 06035C221KAT2A
C49 = CAP_NP: CAP, 0603 47nF 10% 25V X7R; Part Number: AVX 06033C473KAT2A
J11 = BNC5-SCH_15: CONN, BNC, 5 PINS; Part Number: AMPHENOL CONNEX 112404; Pin Numbers Visible: <Pin Numbers Visible>
J12 = BNC5-SCH_16: CONN, BNC, 5 PINS; Part Number: AMPHENOL CONNEX 112404
L5 = IND-TDK-VLF: IND, 68uH; 5TH PART FIELD: SUMIDA CDRH105; Part Number: SUMIDA CDRH105RNP-680N
Q23 Q24 = 2N7002_13: XSTR, MOSFET, N-CHANNEL 30V; Part Number: VISHAY SUD50N03-10CP-E3
R85 = RES0603_5: RES, 2512 OPTION; Label: 1W; Manufacturer: VISHAY; Manufacturer P/N: CRCW251230R0JNEG; Part Number: OPTION; Tolerance: 5%
R87 = RESISTOR_1: RES, 0603 OPTION; Part Number: OPTION
R89 = RES0603_0: RES, 0603 2 OHMS 5% 0.1W; Manufacturer: ROHM; Manufacturer P/N: MCR03EZPFX4991; Part Number: VISHAY CRCW06032R00JNEA; Vendor: Digikey; Vendor P/N: RHM4.99KHCT-ND; Volts/Amps/Watts: 0.1w
R92 = RES0603_0: RES, 0603 3.3 OHMS 1% 0.1W; Manufacturer: ROHM; Manufacturer P/N: MCR03EZPFX4991; Part Number: VISHAY CRCW06033R30FNEA; Tolerance: 1%; Vendor: Digikey
R93 = RES0603_0: RES, 0603 154K OHMS 5% 0.1W; Component: res; Label: <label>; Manufacturer: Panasonic; Manufacturer P/N: ERJ-3EKF5901V; Part Number: VISHAY CRCW0603154KJNEA; Tolerance: 1%; Vendor: Digikey; Vendor P/N: P5.90KHCT-ND; Volts/Amps/Watts: 0.1W
R94 = RES0603_0: RES, 0603 1M OHMS 5% 0.1W; Label: OPT 0; Manufacturer: Rohm; Manufacturer P/N: RHM0.0GCT-ND; Part Number: VISHAY CRCW06031M00JNEA; Vendor: Digikey
R97 = RES0603_0: RES, 0603 681K OHMS 1% 0.1W; Manufacturer: ROHM; Manufacturer P/N: MCR03EZPFX4991; Part Number: VISHAY CRCW0603681KFKEA; Tolerance: 1%
R98 = RES0603_0: RES, 0603 10K OHMS 5% 0.1W; Manufacturer: Panasonic; Manufacturer P/N: ERJ-3EKF2002V; Part Number: VISHAY CRCW060310K0JNEA; Vendor: Digikey
R99 = RES0603_0: RES, 0603 301 OHMS 1% 0.1W; Manufacturer: ROHM; Manufacturer P/N: MCR03EZPFX4991; Part Number: VISHAY CRCW0603301RFKEA; Vendor: Digikey; Vendor P/N: RHM4.99KHCT-ND; Volts/Amps/Watts: 0.1w
R100 = RES0603_0: RES, 0603 82.5 OHMS 5% 0.1W; Manufacturer: ROHM; Manufacturer P/N: MCR03EZPFX4991; Part Number: VISHAY CRCW060382R5FKEA; Tolerance: 1%; Vendor: Digikey
R101 R102 = RES0603_5: RES, 2512 0.01 OHMS 1% 1W; Label: 1W; Manufacturer: VISHAY; Manufacturer P/N: CRCW251230R0JNEG; Part Number: VISHAY WSL2512R0100FEA; Tolerance: 5%
R103 = POT: RES, VARIABLE 5K; Part Number: BOURNS 3386P-1-502-LF
R104 = RES0603_0: RES, 0603 1.21K OHMS 1% 0.1W; Manufacturer: ROHM; Manufacturer P/N: MCR03EZPFX4991; Part Number: VISHAY CRCW06031K21FKEA; Vendor: Digikey; Vendor P/N: RHM4.99KHCT-ND; Volts/Amps/Watts: 0.1w
R105 = RESISTOR_1: RES, 0603 118K OHM 1% 0.1W; Part Number: VISHAY CRCW0603118KFKEA; Tolerance: 1%
R106 = AAC-0603: RES, 0603 80.6k OHMS 1% 0.1W; 1ST PART FIELD: 1%; Part Number: VISHAY CRCW060380K6FKEA
U4 = LTC3630EMSE_0: IC, SYNCHRONOUS STEP-DOWN CONVERTER; Part Number: LINEAR TECH. LTC3630EMSE
U5 = LT1129CS8-3_1.3: IC, TIMER BLOX: VOLTAGE CONTROLLED (PWM); Part Number: LINEAR TECH. LTC6992IS6-1
U6 = LT1129CS8-3_2.3: IC, OP AMP; Part Number: LINEAR TECH. LT1803IS5
D6 D9 = DIODE-LED_2: LED, 0603 GREEN; Manufacturer: PANASONIC; Manufacturer P/N: LN1371SGTRP; Part Number: WURTH ELEKTRONIK 150060GS75000
D7 = DIODE-LED_2: LED, 0603 RED; Label: GREEN; Manufacturer: PANASONIC; Part Number: WURTH ELEKTRONIK 150060SS75000
D11 = DIODE_SCHOTTKY_9: DIODE, SCHOTTKY 30V, 100mA OPTION; Part Number: CENTRAL SEMI CMDSH-3-TR OPTION
D13 = DIODE_SCHOTTKY_0: DIODE, ULTRA LOW  SCHOTTKY RECTIEIER; Part Number: NXP SEMI. PMEG2005AEL,315
J13 = PMBUS_CONNECTOR20_3: CONN, SOCKET 14PIN  DUAL ROW R/A; Component: con; Manufacturer: Mill Max; Manufacturer P/N: 803-93-020-20-001; Part Number: SULLINS INC. NPPN072FJFN-RC; Part Type: HDR2X10RA; Type: conn  RA 20 dual row; Vendor: LTC; Vendor P/N: 803-93-020-20-001
J14 = HD2X6-079-PMBUS_2: HEADER, 12PIN 2mm STR DL; Label: DC1427A HEADER; Manufacturer: MOLEX; Manufacturer P/N: 87831-1220; Part Number: FCI 98414-G06-12ULF; Type: header 12POS 2MM VERT; Vendor: Digikey; Vendor P/N: WM18561-ND
J15 = PMBUS_HEADER20_3: HEADER, 14PIN DUAL ROW R/A; Component: con; Manufacturer: Mill Max; Manufacturer P/N: 802-40-020-20-0001; Part Number: MOLEX 87760-1416; Part Type: HDR_2X10_RA_REV; Type: header RA 20 dual row; Vendor: LTC; Vendor P/N: 802-40-020-20-001
J16 = HD2X6-079-PMBUS_4: HEADER, 4PIN 2mm STR DL; Manufacturer: Hirose; Part Number: HIROSE DF3A-4P-2DSA; Type: header 4POS 2MM VERT
Q20 Q29 = P-MOSFET: XSTR, P-CHANNEL DMOS FET; Part Number: DIODES INC. DMP3130L-7
Q21 Q26 = TRANSISTOR_0: XSTR, N-CHANNEL DMOS FET; Part Number: FAIRCHILD 2N7002A
R70 = RES0603_1: RES, 0603 10 OHMS 5% 0.1W; Manufacturer: Rohm; Manufacturer P/N: RHM0.0GCT-ND; Part Number: VISHAY CRCW060310R0JNEA; Tolerance: 5%; Vendor: Digikey; Vendor P/N: RHM0.0GCT-ND; Volts/Amps/Watts: 0.1W
R79 R130 = RES0603_0: RES, 0603 200 OHMS 5% 0.1W; Label: OPT 0; Manufacturer: Rohm; Manufacturer P/N: RHM0.0GCT-ND; Part Number: VISHAY CRCW0603200RJNEA; Tolerance: 5%; Vendor: Digikey; Vendor P/N: RHM0.0GCT-ND; Volts/Amps/Watts: 0.1W
R81 = RES0603_0: RES, 0603 127 OHMS 1% 0.1W; Label: OPT 0; Manufacturer: Rohm; Manufacturer P/N: RHM0.0GCT-ND; Part Number: VISHAY CRCW0603127RFKEA; Tolerance: 5%; Vendor: Digikey; Vendor P/N: RHM0.0GCT-ND; Volts/Amps/Watts: 0.1W
R122 = RES0603_3: RES, 0603 OPTION; Label: OPT 0; Manufacturer: Rohm; Manufacturer P/N: RHM0.0GCT-ND; Part Number: OPTION; Tolerance: 5%; Vendor: Digikey; Vendor P/N: RHM0.0GCT-ND; Volts/Amps/Watts: 0.1W
R123 = RES0603_11: RES, 0603 10K OHMS 5% 0.1W; Part Number: VISHAY CRCW060310K0JNEA
R128 R150 = RES0603_0: RES, 0603 4.99K OHMS 1% 0.1W; Manufacturer: ROHM; Manufacturer P/N: MCR03EZPFX4991; Part Number: VISHAY CRCW06034K99FKEA; Vendor: Digikey; Vendor P/N: RHM4.99KHCT-ND; Volts/Amps/Watts: 0.1w
R136 R142 R145 R151 = RES0603_0: RES, 0603 OPTION; Label: OPT 0; Manufacturer: Rohm; Manufacturer P/N: RHM0.0GCT-ND; Part Number: OPTION; Tolerance: 5%; Vendor: Digikey; Vendor P/N: RHM0.0GCT-ND; Volts/Amps/Watts: 0.1W
R137 R138 = RES0603_0: RES, 0603 0 OHMS JUMPER; Label: OPT 0; Manufacturer: Rohm; Manufacturer P/N: RHM0.0GCT-ND; Part Number: VISHAY CRCW06030000Z0EA; Tolerance: 5%; Vendor: Digikey; Vendor P/N: RHM0.0GCT-ND; Volts/Amps/Watts: 0.1W
R139 = RES0603_3: RES, 1206 OPTION; Label: OPT 0; Manufacturer: Rohm; Manufacturer P/N: RHM0.0GCT-ND; Part Number: OPTION; Tolerance: 5%; Vendor: Digikey; Vendor P/N: RHM0.0GCT-ND; Volts/Amps/Watts: 0.1W
R147 = RES0603_11: RES, 0603 15.8K OHMS 1% 0.1W; Part Number: VISHAY CRCW060315K8FKEA
SW2 = JP3X1_079_NO_12_3: SWITCH, SUBMINATURE SLIDE; Part Number: C&K JS202011CQN
U8 = 24LC025-I_SN: IC, SERIAL EEPROM; Part Number: MICROCHIP 24LC024-I/ST
J6A J6B J7A J7B J40A J50A J50B J100 J101 J200 J201 J300 J301 J400 = NUT: NUT, BRASS 10-32; Part Number: ANY #10-32
J6C J7C J20A J30A J40B J50C J101A = Lug_Ring: LUG RING, #10; Part Number: KEYSTONE 8205
J7D J20B J30B J40C J50D J60 J101B = Washer: WASHER, #10 TIN PLATED BRASS; Part Number: ANY #10 EXT BZ TN
MH1-MH4 = CON1: STANDOFF, SNAP ON; Part Number: KEYSTONE 8834

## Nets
3V3: J14.5(LGKPWR) Q20.2(S) Q29.3(D) R79.1 R130.1 R151.1
+5.5V: C30.1 C41.2 C44.1 C51.1 L5.2 R87.1 R91.2 R94.1 R105.2
GND_POWER: C2.2 C3.1 C4.1 C6.1 C18.2 C19.1 C20.2 C28.2 C30.2 C31.2 C34.2 C35.2 C39.2 C41.1 C42.1 C43.2 C44.2 C46.2 C47.2 C48.1 C49.2 C50.2 C52.2 C53.2 C54.2 CIN1.2 CIN2.2 CIN3.2 CIN4.2 CIN5.2 CIN6.2 CIN7.2 CIN8.2 CIN9.2 CIN10.2 CIN11.2 CIN12.2 CIN13.2 CIN14.2 CIN15.2 CIN16.2 CIN21.2 CIN22.2 CIN23.2 CIN24.2 CIN25.2 CIN26.2 CIN27.2 CIN28.2 COUT1.2 COUT2.2 COUT3.2 COUT4.2 COUT5.2 COUT6.2 COUT7.2 COUT8.2 COUT9.2 COUT10.2 COUT11.2 COUT12.2 COUT13.2 COUT14.2 COUT15.2 COUT16.2 COUT17.2 COUT18.2 COUT19.2 COUT20.2 COUT22.2 COUT23.2 COUT24.2 COUT25.2 COUT26.1 COUT27.2 COUT28.2 COUT29.2 COUT30.2 COUT31.2 COUT32.2 COUT33.2 COUT34.2 COUT35.2 COUT36.2 COUT37.2 COUT38.2 COUT39.2 COUT40.2 COUT41.2 E2.1(A) E8.1(A) E21.1(A) J2.1(TP) J4.1(TP) J6.1(TP) J11.2 J11.3(GND_POWER) J11.4(GND_POWER) J11.5(GND_POWER) J12.2 J12.3(GND_POWER) J12.4(GND_POWER) J12.5(GND_POWER) J13.11(GND) J13.12(GND) J14.3(GND) J14.10(GND) J15.11(GND) J15.12(GND) J16.2(GND) JP4.3 Q1.10(S) Q2.10(S) Q3.10(S) Q4.10(S) Q5.10(S) Q6.10(S) Q7.10(S) Q8.10(S) Q11.10(S) Q12.10(S) Q13.10(S) Q14.10(S) Q21.2(S) Q26.2(S) R16.1 R81.2 R85.1 R96.1 R97.2 R98.1 R101.1 R102.1 R103.1(A) R103.2(WIPER) R104.2 R106.2 R107.1 R147.2 SW2.3 U1.41(PGND) U1.49(GND) U2.29(GND) U4.6(VPRG2) U4.7(VPRG1) U4.8(GND) U4.14(GND) U4.16(GND) U4.17(GND) U5.2(GND) U6.2(V-) U7.29(GND) U8.1(A0) U8.2(A1) U8.3(A2) U8.4(VSS) U8.7(WP)
GND_SIGNAL: C1.1 C7.1 C12.1 C13.1 C14.2 C17.2 C23.1 C45.1 JP1.3 JP2.3 JP3.3 Q9.1(B) Q9.3(C) Q10.1(B) Q10.3(C) R23.2 R26.2 R28.2 R32.2 R36.2 R38.2 R55.1 R58.1 R59.1 R108.1
VDD25: C7.2 R22.1 R25.1 R27.1 R31.1 R35.1 R37.1 U1.25(VDD25)
VDD33: C1.2 D13.1(CATHODE) Q29.2(S) R6.2 R8.2 R9.2 R10.2 R11.1 R12.2 R13.1 R29.2 R34.2 U1.28(VDD33)
VIN: C2.1 C31.1 C52.1 C53.1 C54.1 E1.1(A) J1.1(TP) R1.1 R2.1 R4.2 R49.1 R50.1 R123.1 R139.1 R159.1 U4.3(VIN)
VIN1: CIN1.1 CIN2.1 CIN3.1 CIN4.1 CIN5.1 CIN6.1 CIN7.1 CIN8.1 CIN9.1 CIN10.1 CIN11.1 CIN12.1 CIN13.1 CIN14.1 CIN15.1 CIN16.1 CIN21.1 CIN22.1 CIN23.1 CIN24.1 CIN25.1 CIN26.1 CIN27.1 CIN28.1 Q1.3(D) Q1.4(D) Q1.9(D) Q2.3(D) Q2.4(D) Q2.9(D) Q3.3(D) Q3.4(D) Q3.9(D) Q4.3(D) Q4.4(D) Q4.9(D) Q5.3(D) Q5.4(D) Q5.9(D) Q6.3(D) Q6.4(D) Q6.9(D) Q7.3(D) Q7.4(D) Q7.9(D) Q8.3(D) Q8.4(D) Q8.9(D) Q11.3(D) Q11.4(D) Q11.9(D) Q12.3(D) Q12.4(D) Q12.9(D) Q13.3(D) Q13.4(D) Q13.9(D) Q14.3(D) Q14.4(D) Q14.9(D) R1.2 R3.2 R159.2
AC_DC: JP2.2 U2.27(LOWDCR) U7.27(LOWDCR)
ALERTB: E22.1(A) J13.3(ALERTB) J14.6(ALERTB) J15.3(ALERTB) Q20.1(G) R10.1 U1.14(ALERTB)
ASEL0: R22.2 R23.1 U1.19(ASEL0)
ASEL1: R25.2 R26.1 U1.20(ASEL1)
AUX3V4: D13.2(ANODE) J16.4(AUX3V4)
AUXVCC: C50.1 E36.1(A) J13.8(AUXP) J14.1(AUXP) J15.8(AUXP) R128.1 R150.1 U8.8(VCC)
BG1: Q3.8(BG) Q4.8(BG) U1.37(BG1)
BG3: Q7.8(BG) Q8.8(BG) U2.17(BG1)
BG5: Q13.8(BG) Q14.8(BG) U7.17(BG1)
BST0: R15.1 U1.43(BOOST0)
BST1: R19.1 U1.36(BOOST1)
BST2: R53.1 U2.22(BOOST0)
BST3: R140.1 U2.16(BOOST1)
BST4: R54.1 U7.22(BOOST0)
BST5: R60.1 U7.16(BOOST1)
EESCL: J14.11(AUXSCL) R128.2 U8.6(SCL)
EESDA: J14.12(AUXSDA) R150.2 U8.5(SDA)
EXTVCC: C6.2 C20.1 C46.1 R87.2 U1.40(EXTVCC) U2.18(EXTVCC) U7.18(EXTVCC)
FAULT: D11.2(ANODE) E28.1(A) Q21.1(G) R29.1 R30.2 R138.2 U1.15(\\~{FAULT}0) U2.25(\\~{FAULT1}) U2.26(\\~{FAULT0}) U7.25(\\~{FAULT1}) U7.26(\\~{FAULT0})
FREQ_CFG: R35.2 R36.1 U1.23(FREQ_CFG)
ILIM: JP3.2 U2.11(ILIM) U7.11(ILIM)
INTVCC1: C4.2 D1.2(ANODE) D2.2(ANODE) U1.38(INTVCC)
INTVCC2: C18.1 D3.2(ANODE) D4.2(ANODE) JP2.1 JP3.1 R56.2 U2.19(INTVCC)
INTVCC3: C47.1 D8.2(ANODE) D12.2(ANODE) R158.2 U7.19(INTVCC)
ITH: C12.2 C23.2 C45.2 U1.6(ITH0) U1.29(ITH1) U2.9(ITH1) U2.28(ITH0) U7.9(ITH1) U7.28(ITH0)
PGOOD: E37.1(A) Q26.1(G) R34.1 U1.33(PGOOD1) U1.48(PGOOD0) U2.1(MODE0) U2.8(MODE1) U7.1(MODE0) U7.8(MODE1)
PHASE_CFG: R37.2 R38.1 U1.24(PHASE_CFG)
RUN: D11.1(CATHODE) E34.1(A) R8.1 R51.1 R52.1 R70.2 R83.1 R84.1 R137.2 R142.2 SW2.1 SW2.2 U1.17(RUN0) U1.18(RUN1)
SCL: E24.1(A) J13.6(SCL) J14.4(SCL) J15.6(SCL) J16.3(SCL) R12.1 U1.12(SCL)
SDA: E23.1(A) J13.4(SDA) J14.2(SDA) J15.4(SDA) J16.1(SDA) R11.2 U1.13(SDA)
SHARE_CLK: E25.1(A) R9.1 R127.1 U1.27(SHARE_CLK)
SW0: L1.1 Q1.5(PH) Q1.6(PH) Q1.7(PH) Q2.5(PH) Q2.6(PH) Q2.7(PH) R14.1
SW1: L2.1 Q3.5(PH) Q3.6(PH) Q3.7(PH) Q4.5(PH) Q4.6(PH) Q4.7(PH) R20.1
SW2: L3.1 Q5.5(PH) Q5.6(PH) Q5.7(PH) Q6.5(PH) Q6.6(PH) Q6.7(PH) R135.1
SW3: L4.1 Q7.5(PH) Q7.6(PH) Q7.7(PH) Q8.5(PH) Q8.6(PH) Q8.7(PH) R143.1
SW4: L6.1 Q11.5(PH) Q11.6(PH) Q11.7(PH) Q12.5(PH) Q12.6(PH) Q12.7(PH) R157.1
SW5: L7.1 Q13.5(PH) Q13.6(PH) Q13.7(PH) Q14.5(PH) Q14.6(PH) Q14.7(PH) R144.1
SYNC: E26.1(A) R13.2 R145.1 U1.11(SYNC) U2.12(SYNC) U7.12(SYNC)
TG0: Q1.1(TG) Q2.1(TG) U1.44(TG0)
TG1: Q3.1(TG) Q4.1(TG) U1.35(TG1)
TG2: Q5.1(TG) Q6.1(TG) U2.24(TG0)
TG3: Q7.1(TG) Q8.1(TG) U2.14(TG1)
TG4: Q11.1(TG) Q12.1(TG) U7.24(TG0)
TG5: Q13.1(TG) Q14.1(TG) U7.14(TG1)
VOUT: C34.1 C35.1 COUT1.1 COUT2.1 COUT3.1 COUT4.1 COUT5.1 COUT6.1 COUT7.1 COUT8.1 COUT9.1 COUT10.1 COUT11.1 COUT12.1 COUT13.1 COUT14.1 COUT15.1 COUT16.1 COUT17.1 COUT18.1 COUT19.1 COUT20.1 COUT22.1 COUT23.1 COUT24.1 COUT25.1 COUT26.2 COUT27.1 COUT28.1 COUT29.1 COUT30.1 COUT31.1 COUT32.1 COUT33.1 COUT34.1 COUT35.1 COUT36.1 COUT37.1 COUT38.1 COUT39.1 COUT40.1 COUT41.1 J3.1(TP) J5.1(TP) J11.1 L1.2 L2.2 L3.2 L4.2 L6.2 L7.2 Q23.2 Q24.2 R5.2 R85.2 R113.1 R114.1 R117.1 R118.1 R148.1 R149.1
VOUT0_CFG: R27.2 R28.1 U1.21(VOUT0_CFG)
VOUT1_CFG: R31.2 R32.1 U1.22(VOUT1_CFG)
VSENSE+: E3.1(A) R5.1 U1.1(VSENSE0+) U1.32(VSENSE1+)
VSENSE-: E4.1(A) R16.2 U1.2(VSENSE0-) U1.31(VSENSE1-)
WP1: JP1.2 R6.1 U1.26(WP)
N19055332: C3.2 R2.2 U1.39(VIN)
N19064724: C5.1 R3.1 U1.47(IIN-)
N19065153: C5.2 R4.1 U1.46(IIN+)
N19167019: C13.2 U1.5(ITH_R0) U1.30(ITH_R1)
N19178028: C17.1 Q9.2(E) U1.9(TSNS1)
N19241863: C14.1 Q10.2(E) U1.10(TSNS0)
N19269991: C8.1 Q1.2(PH) Q2.2(PH) U1.45(SW0)
N19298372: C8.2 D1.1(CATHODE) R15.2
N19417825: C9.1 R14.2 R17.1 U1.7(ISENSE0+)
N19418952: C9.2 R17.2 R113.2 U1.8(ISENSE0-)
N19478844: C15.1 Q3.2(PH) Q4.2(PH) U1.34(SW1)
N19478879: C15.2 D2.1(CATHODE) R19.2
N19489859: C16.1 R20.2 R24.1 U1.3(ISENSE1+)
N19491163: C16.2 R24.2 R114.2 U1.4(ISENSE1-)
N19517743: R30.1 U1.16(\\~{FAULT}1)
N19742729: C37.2 D3.1(CATHODE) R53.2
N19742908: C25.2 D4.1(CATHODE) R140.2
N19742939: C21.1 R141.1 R143.2 U2.7(ISENSE1+)
N19742943: C37.1 Q5.2(PH) Q6.2(PH) U2.23(SW0)
N19743193: C25.1 Q7.2(PH) Q8.2(PH) U2.15(SW1)
N19743232: C21.2 R117.2 R141.2 U2.6(ISENSE1-)
N19758120: R52.2 U2.4(RUN0)
N19758540: R51.2 U2.5(RUN1)
N19769419: R55.2 U2.10(FREQ)
N19777670: R56.1 R59.2 U2.13(PHASMD)
N19792058: C33.1 R134.1 R135.2 U2.2(ISENSE0+)
N19792974: C33.2 R134.2 R148.2 U2.3(ISENSE0-)
N19844769: C19.2 R49.2 U2.20(VIN)
N20479472: C40.2 R92.1 U6.1(VOUT)
N20479484: R95.1 R99.1 U6.3(+IN)
N20479490: C39.1 R95.2 U5.6(OUT) U6.5(V+)
N20479492: C42.2 J12.1 Q23.3 Q24.3 R100.2 R101.2 R102.2
N20479647: JP5.2 JP5.3 Q23.1 Q24.1 R89.2 R98.2
N20479673: JP5.1 R92.2
N20479683: E7.1(A) R89.1
N20479716: R94.2 R97.1 U5.4(DIV)
N20479804: R91.1 U5.5(V+)
N20479929: R93.1 R96.2 U5.1(MOD)
N20479960: C40.1 R100.1 U6.4(-IN)
N20480136: R99.2 R103.3(B) R104.1
N20480171: R93.2 U5.3(SET)
N20612248: L5.1 U4.1(SW)
N20614777: JP4.2 U4.5(RUN)
N20633357: C49.1 U4.10(SS)
N20641937: C51.2 R105.1 R107.2 U4.9(VFB)
N20657658: C43.1 R106.1 U4.11(ISET)
N20769452: Q1.8(BG) Q2.8(BG) U1.42(BG0)
N20791643: Q5.8(BG) Q6.8(BG) U2.21(BG0)
N20821299: R108.2 R158.1 U7.13(PHASMD)
N20821313: C32.1 R146.1 R157.2 U7.2(ISENSE0+)
N20821329: C32.2 R146.2 R149.2 U7.3(ISENSE0-)
N20821331: C48.2 R50.2 U7.20(VIN)
N20821379: C27.2 D8.1(CATHODE) R54.2
N20821393: C38.2 D12.1(CATHODE) R60.2
N20821409: C36.1 R144.2 R156.1 U7.7(ISENSE1+)
N20821411: C27.1 Q11.2(PH) Q12.2(PH) U7.23(SW0)
N20821500: Q11.8(BG) Q12.8(BG) U7.21(BG0)
N20821506: C38.1 Q13.2(PH) Q14.2(PH) U7.15(SW1)
N20821563: C36.2 R118.2 R156.2 U7.6(ISENSE1-)
N20821918: R58.2 U7.10(FREQ)
N20822174: R83.2 U7.4(RUN0)
N20822206: R84.2 U7.5(RUN1)
N20847944: D9.2(A) R130.2
N20847953: D9.1(K) Q26.3(D)
N20848126: J13.13(12V) J13.14(12V) J15.13(12V) J15.14(12V) R139.2
N20848139: J13.9(UNUSED) J15.9(UNUSED) R145.2
N20848161: J13.7(RESETB) J15.7(RESETB)
N20848163: J13.5(SHARE_CLK) J15.5(SHARE_CLK) R127.2
N20848169: J13.1(FAULTB) J15.1(FAULTB) R138.1 R142.1
N20848171: J13.10(UNUSED) J15.10(UNUSED) R151.2
N20848177: J13.2(CTRL) J15.2(CTRL) R122.2 R136.2 R137.1
N20848419: C28.1 R70.1
N20848573: J14.8(OUTEN_0) R122.1
N20848575: J14.9(OUTEN_1) R136.1
N20848628: Q29.1(G) R123.2 R147.1
N20849050: D6.2(A) R79.2
N20849078: D6.1(K) Q21.3(D)
N20849159: D7.2(A) Q20.3(D)
N20849178: D7.1(K) R81.1

Not connected (* = marked no-connect by the designer): J14 7(GPIO_1); JP1 1; JP4 1*; MH1 1; MH2 1; MH3 1; MH4 1; SW2 4 5 6; U4 12(FBO)

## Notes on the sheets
sheet 1
- HARDWARE
- STANDOFFS
sheet 2
- 744301025
- 744301025
sheet 3
- OPTIONAL 5.5V BIAS
- OPT
- BIAS
- 2512
- ON
- OFF
- BLEEDER LOADS
- DYNAMIC LOAD CIRCUIT
- VOUT
- PULSE
- INT
- EXT
- 70Hz, 3% Duty Cycle
- IOUT STEP
- 1%
sheet 4
- 10V - 14V
- 744301025
- 1V AT 240A
- WP
- ON
- OFF
- 744301025
sheet 5
- 744301025
- DCR SENSING
- LOWDCR
- NORMAL
- ILIM
- RANGE_HIGH
- RANGE_LOW
- 744301025
sheet 6
- ALL PARTS ON THIS PAGE ARE FOR DEMO BOARD ONLY, NOT NEEDED IN CUSTOMER DESIGN
- TO DC2086A
- RUN
- TO DC1613A
- ON
- OFF
- 1206
- PGOOD
- GPIO
- ALERTB
